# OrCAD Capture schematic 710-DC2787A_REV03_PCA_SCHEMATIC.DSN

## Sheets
1 PAGE5: size A
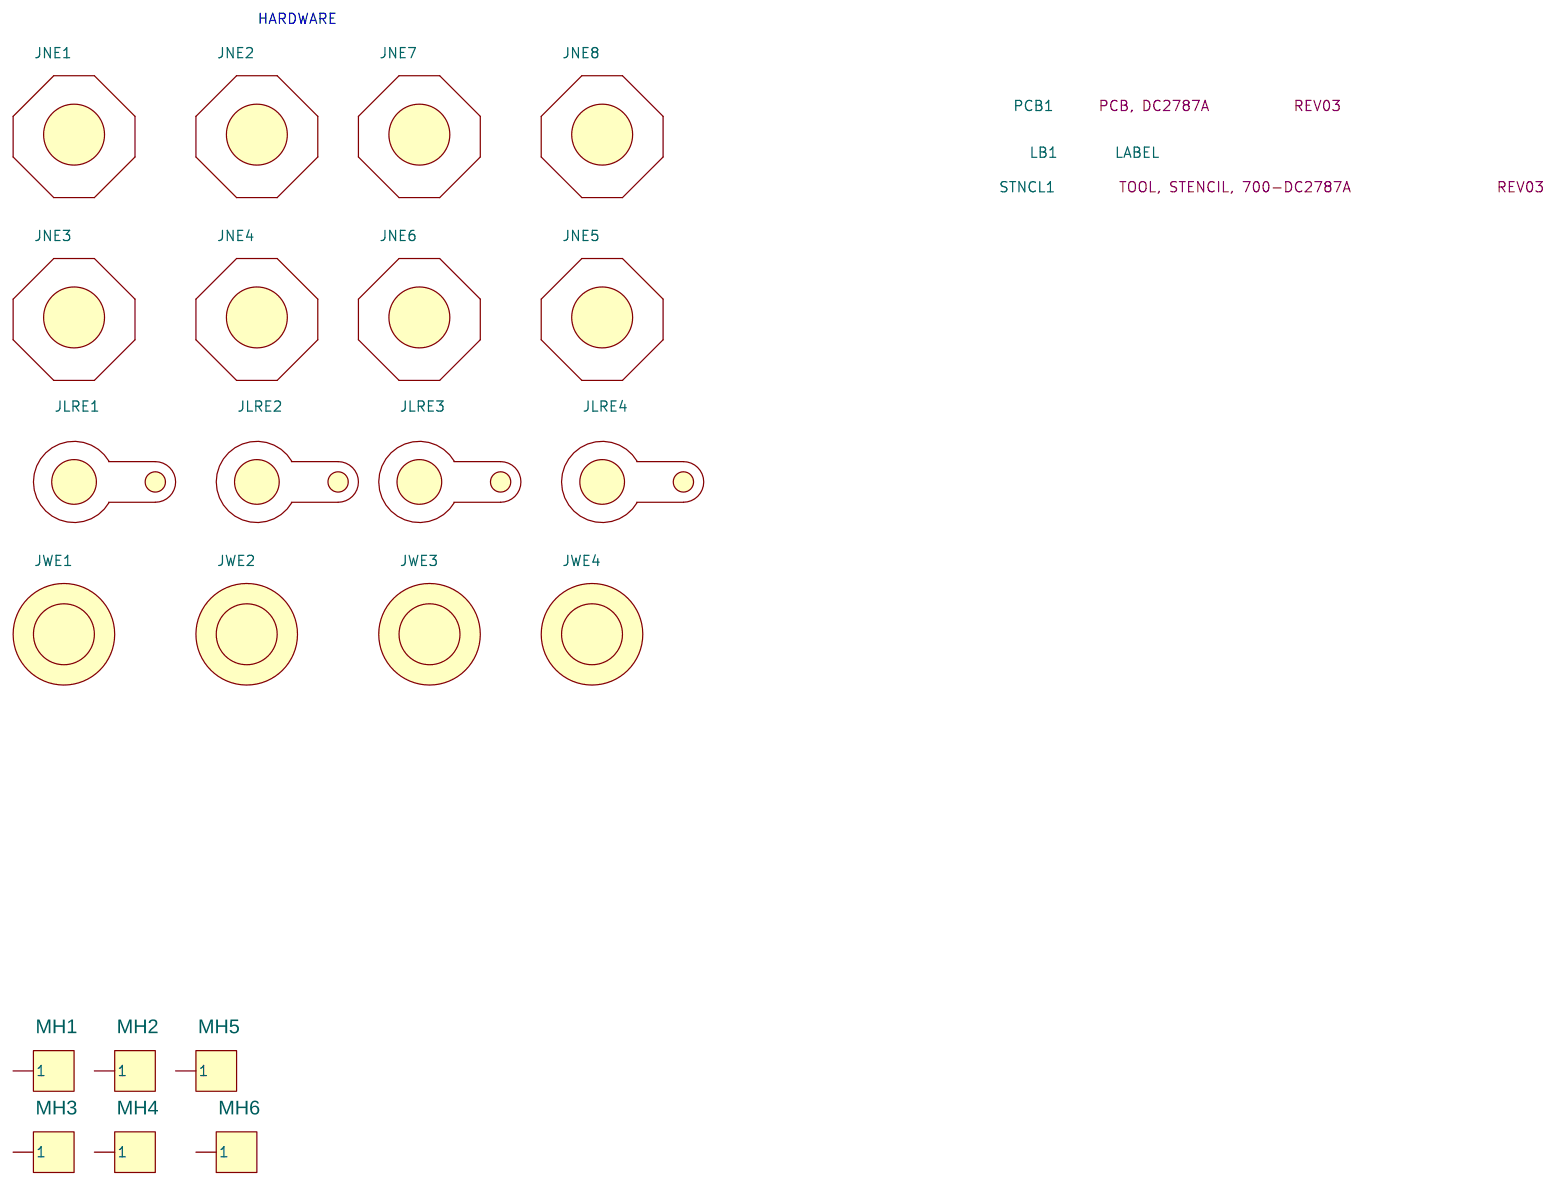
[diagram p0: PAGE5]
2 PAGE4: size Custom; note: HIGH EFFICIENCY, POLYPHASE HYBRID STEP-DOWN
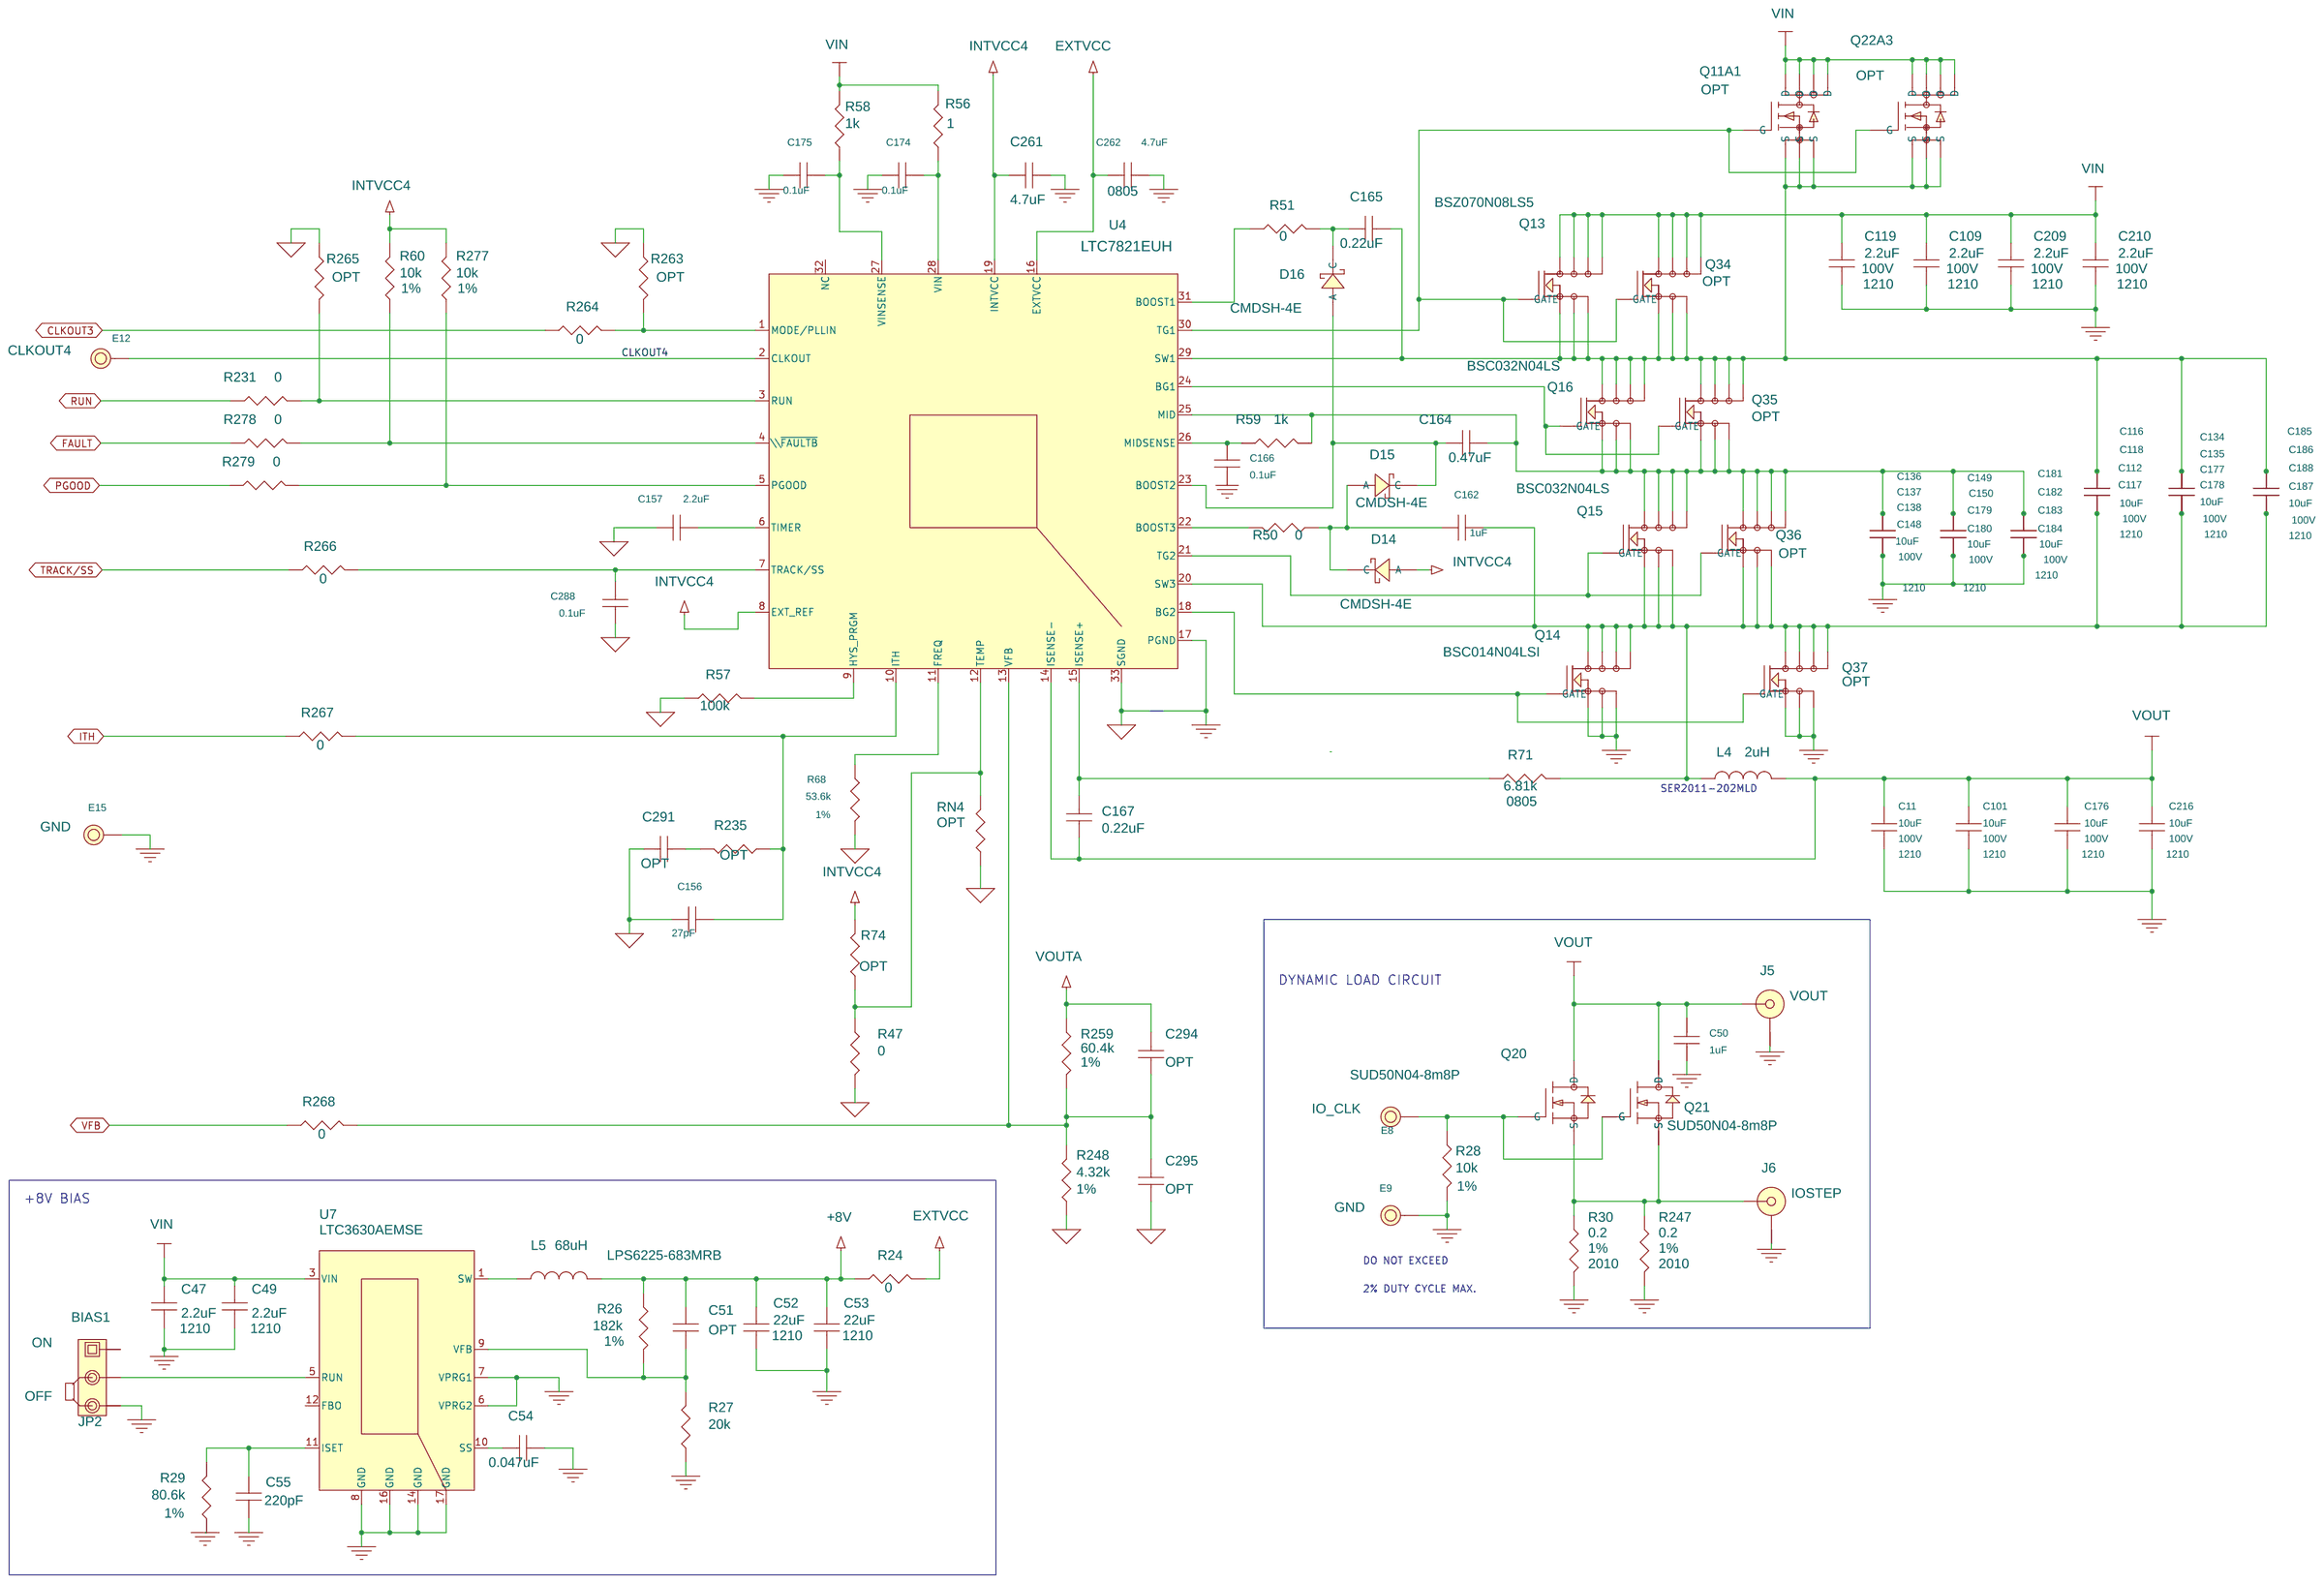
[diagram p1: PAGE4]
3 PAGE3: size Custom; title: HIGH EFFICIENCY, HIGH STEP-DOWN RATIO, SWITCHED CAPACITOR INVERTER; company: LINEAR TECHNOLOGY CORP.; note: DEMO BOARD BILL OF MATERIALS; note: HIGH EFFICIENCY, POLYPHASE HYBRID STEP-DOWN
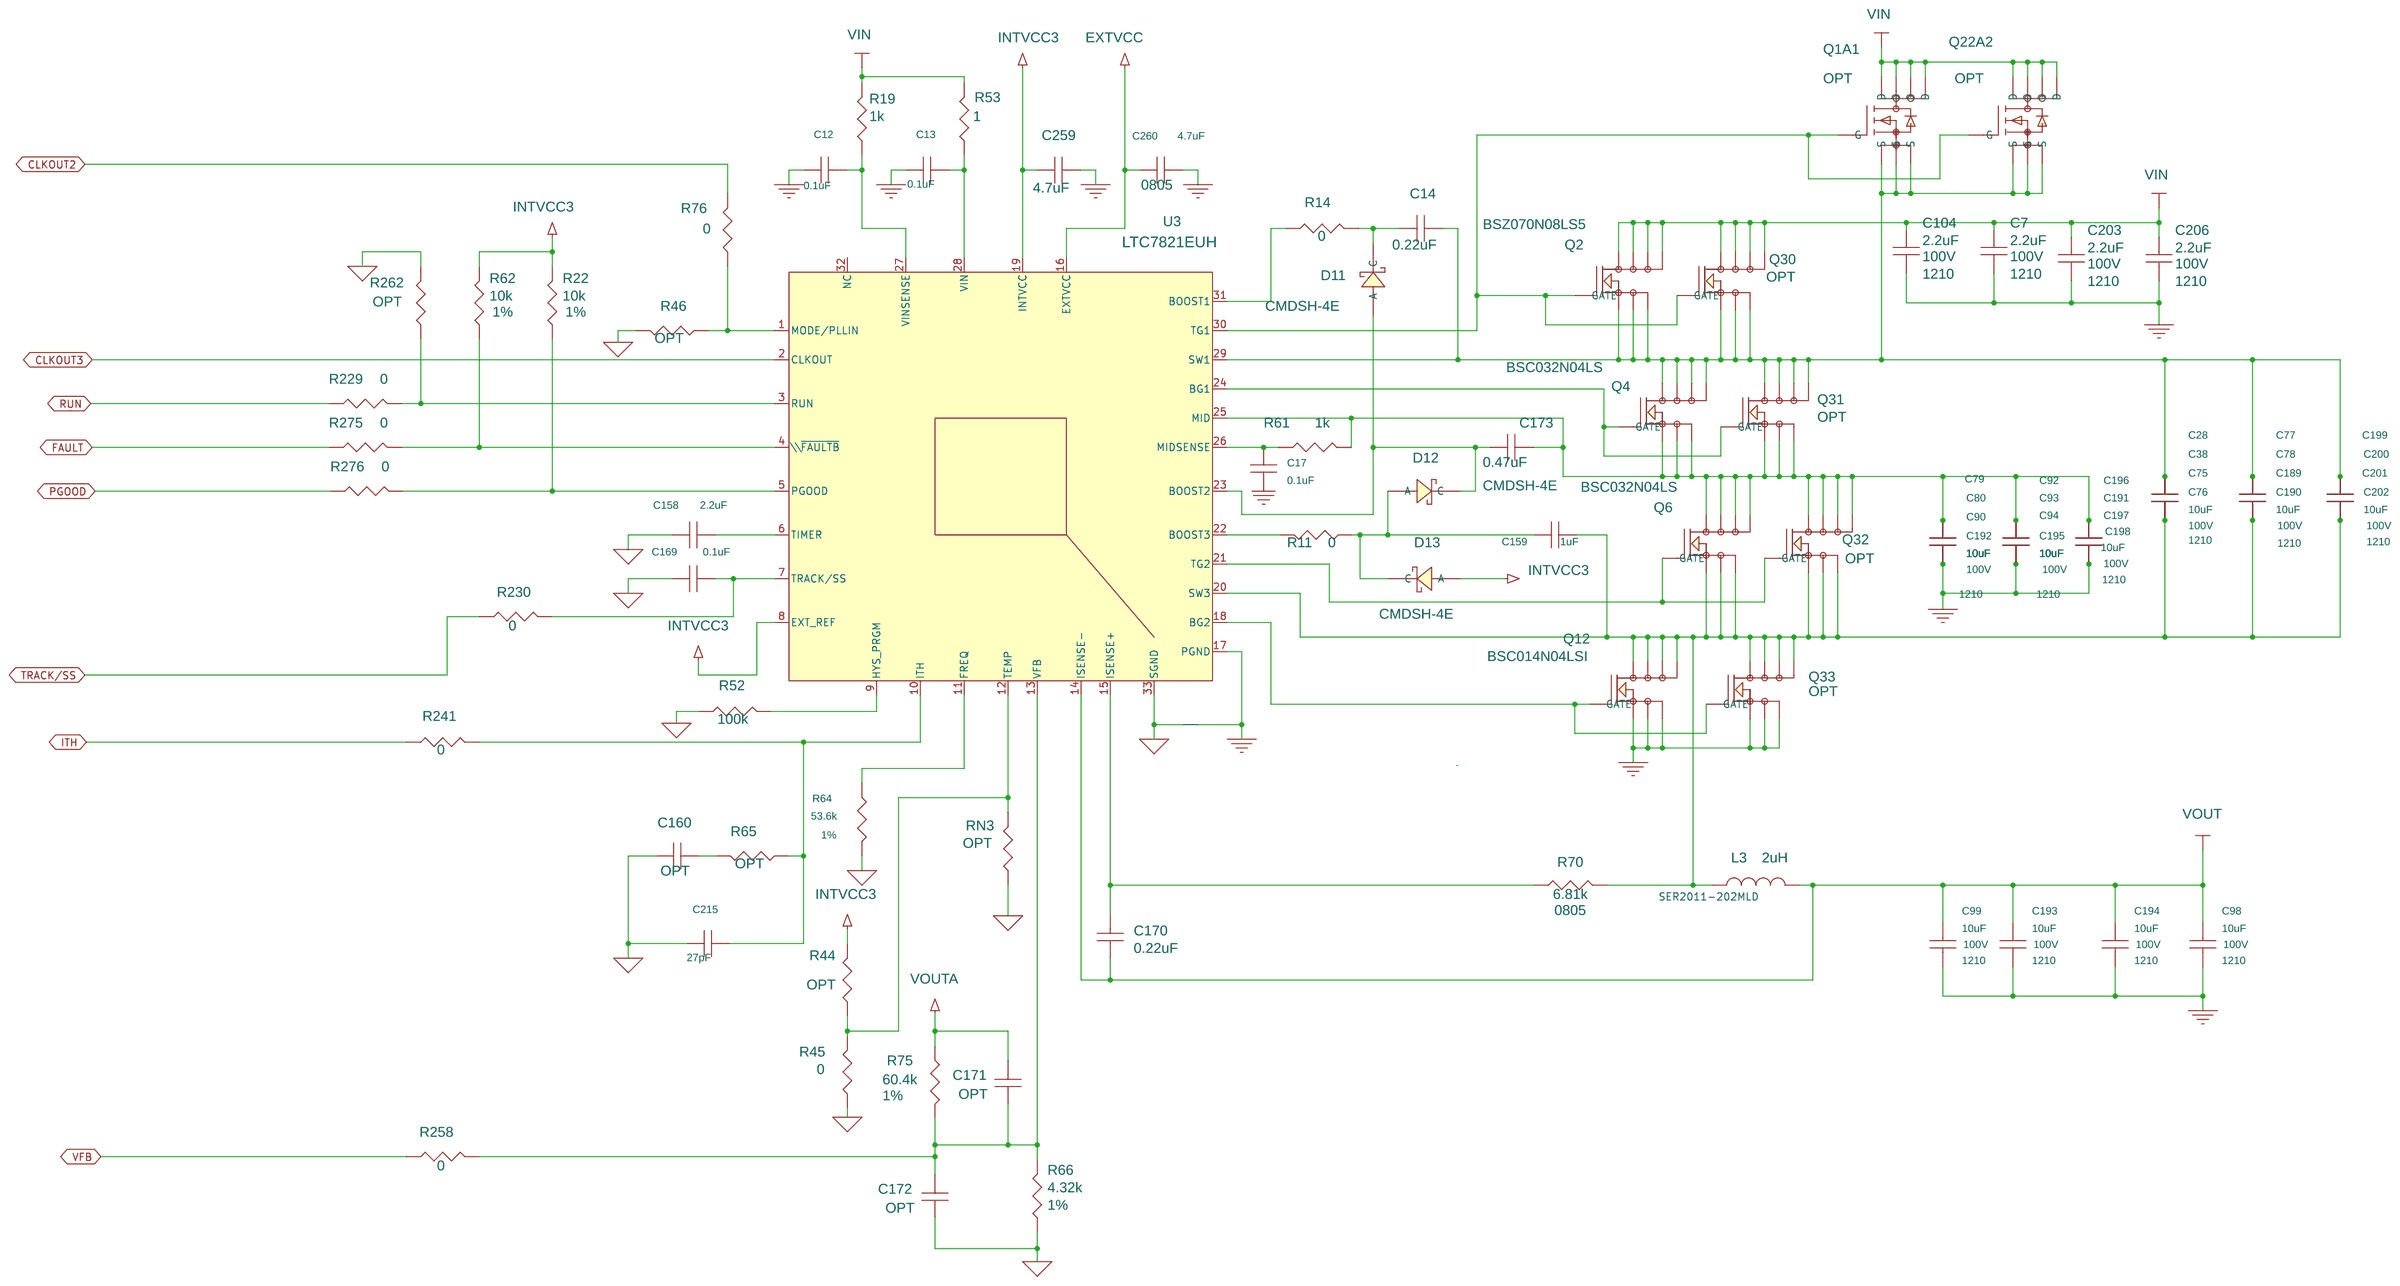
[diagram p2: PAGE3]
4 PAGE2: size Custom; note: HIGH EFFICIENCY, POLYPHASE HYBRID STEP-DOWN
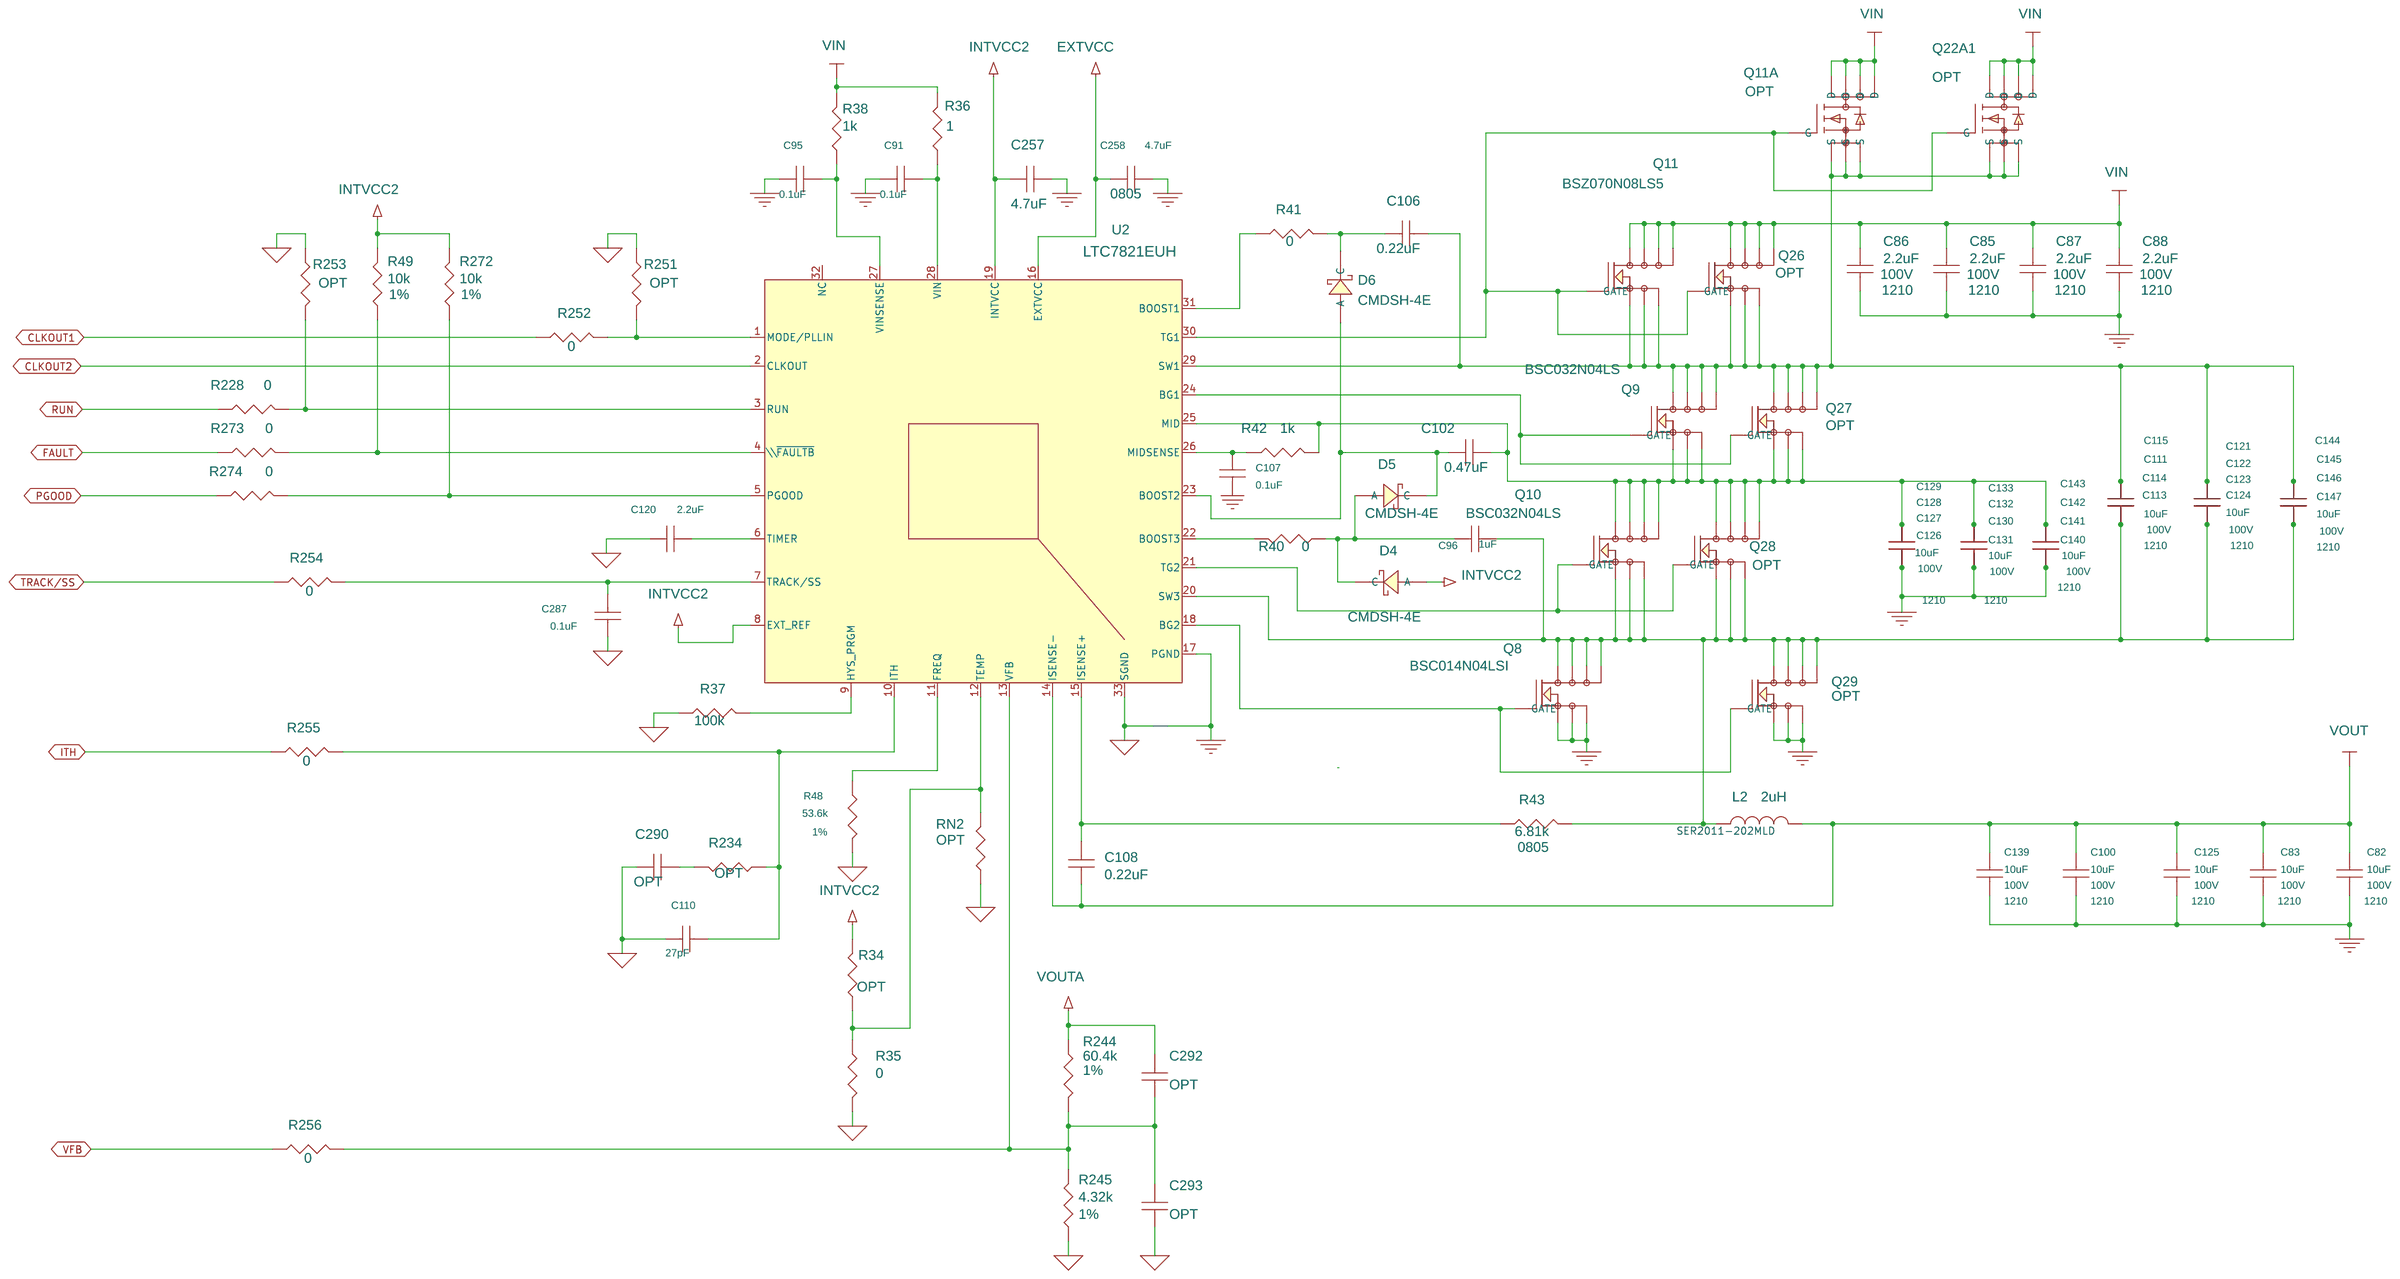
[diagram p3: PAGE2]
5 PAGE1: size Custom; title: HIGH EFFICIENCY, HIGH STEP-DOWN RATIO, SWITCHED CAPACITOR INVERTER; company: LINEAR TECHNOLOGY CORP.; note: DEMO BOARD BILL OF MATERIALS; note: HIGH EFFICIENCY, POLYPHASE HYBRID STEP-DOWN
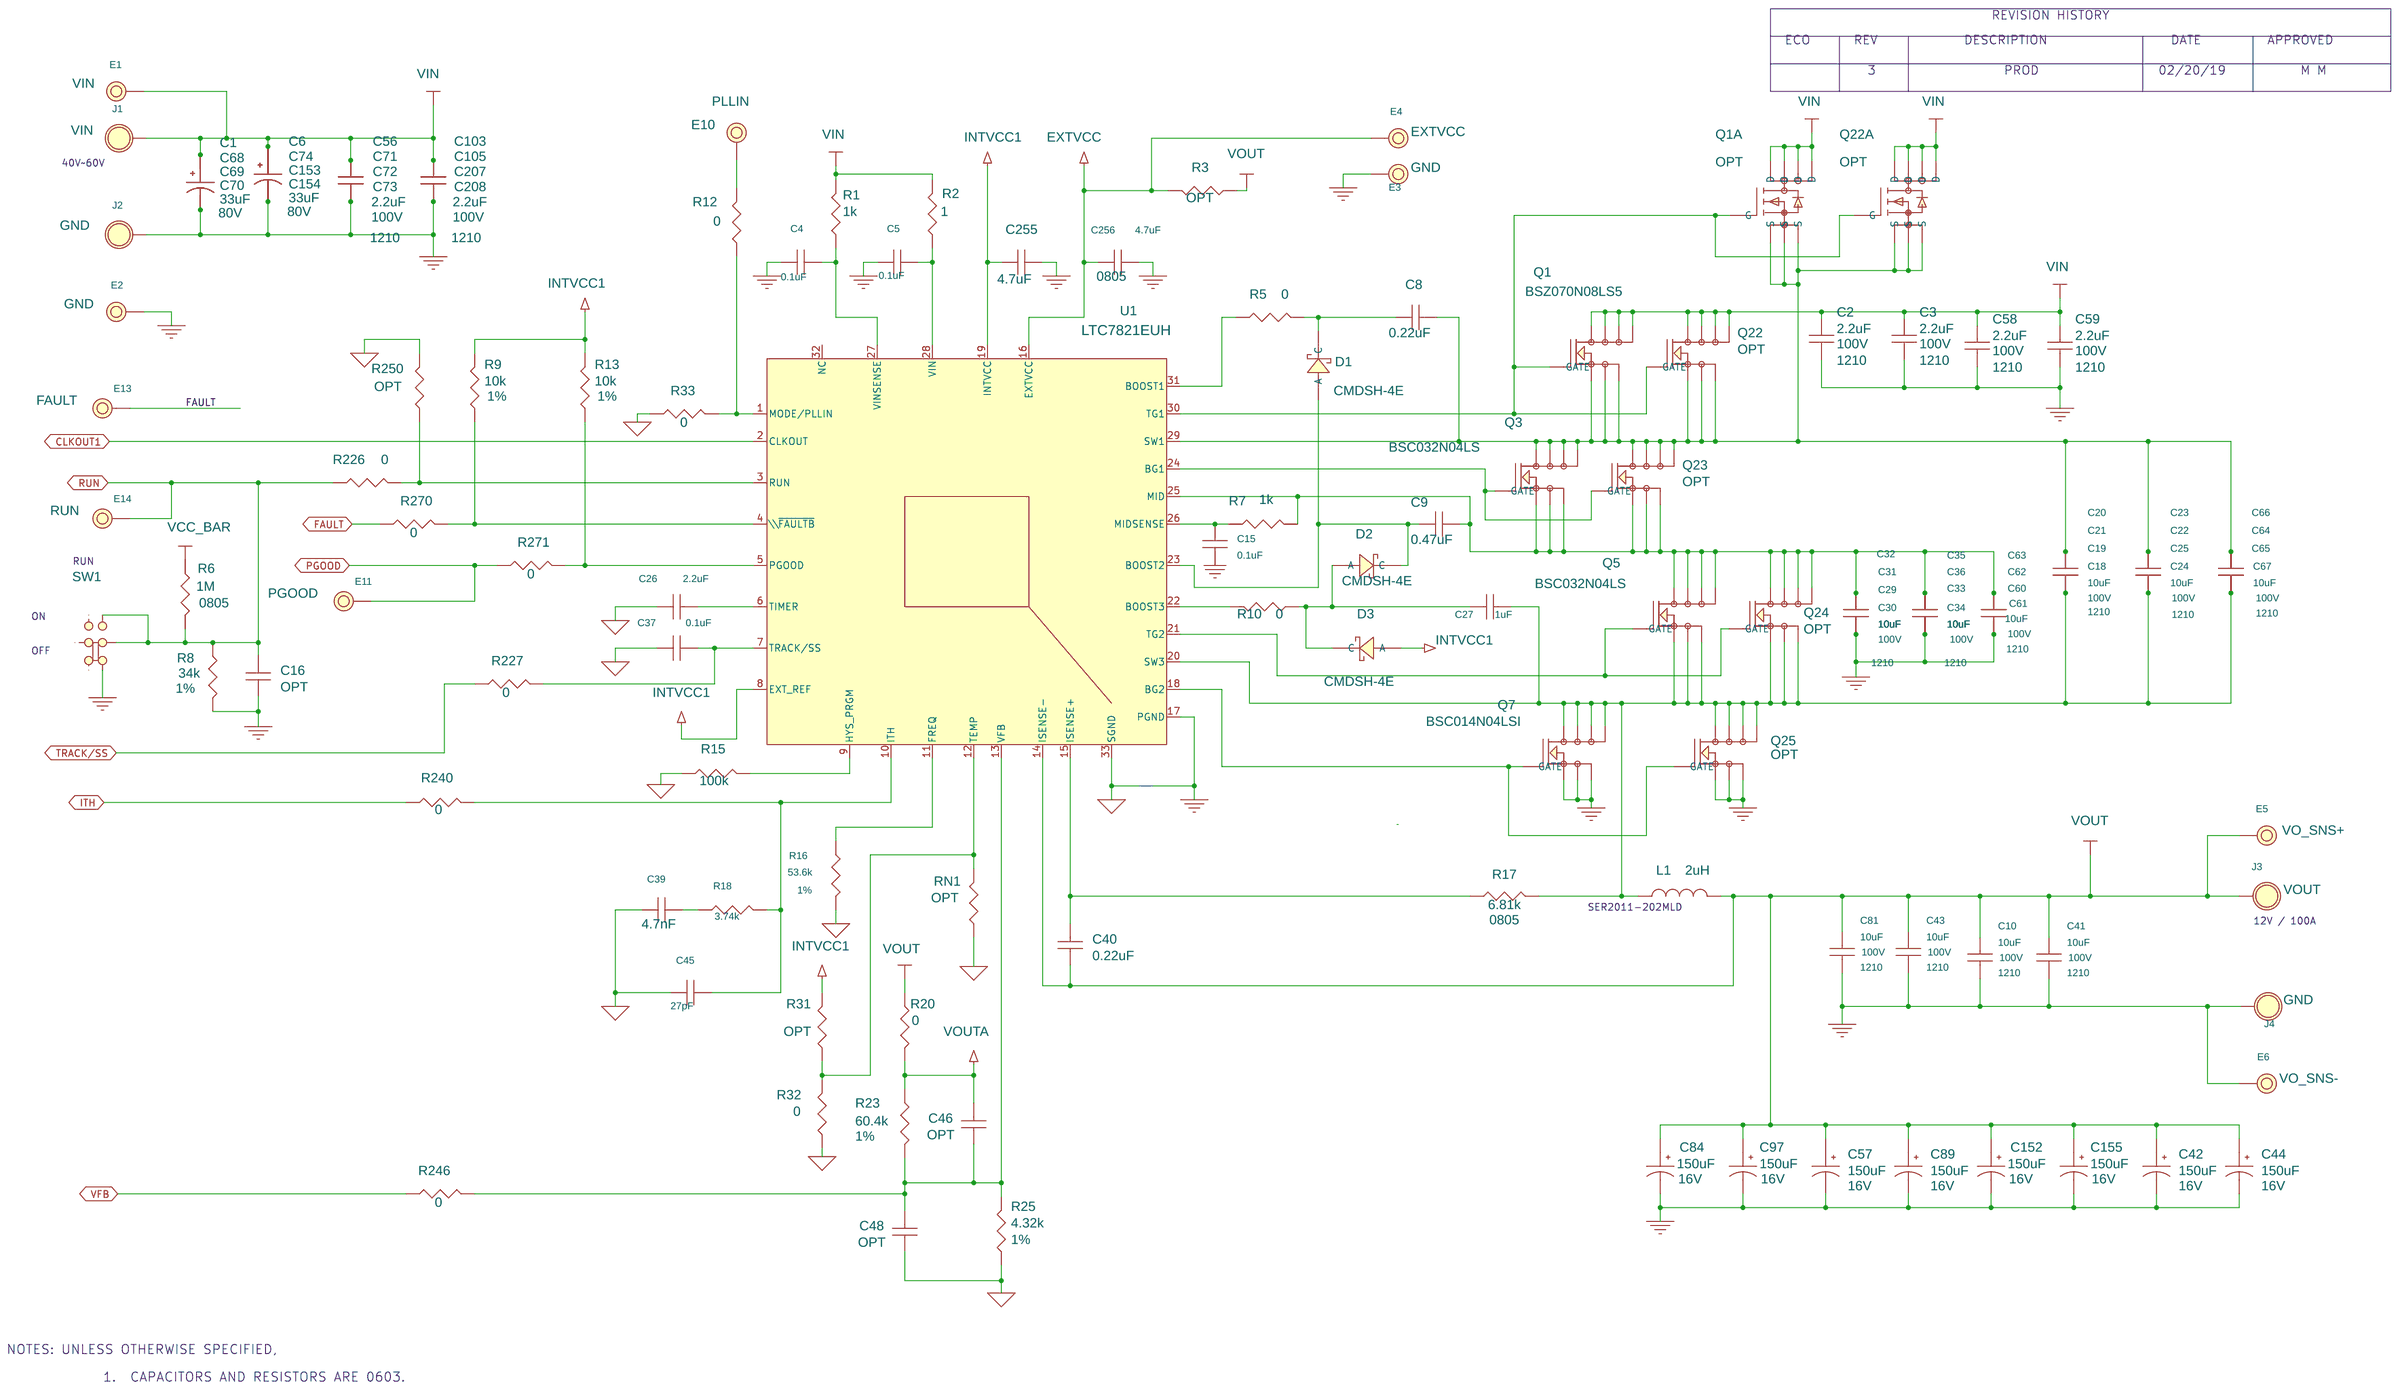
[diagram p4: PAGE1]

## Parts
sheet PAGE1
C1  33uF  [CAP\SANYO\10X10.2\CE]
C2  2.2uF  [CC1210N]
C3  2.2uF  [CC1210N]
C4  0.1uF  [CC0603N]
C5  0.1uF  [CC0603N]
C6  33uF  [CAP\SANYO\10X10.2\CE]
C8  0.22uF  [CC0603N]
C9  0.47uF  [CC0603N]
C10  10uF  [CC1210N]
C15  0.1uF  [CC0603N]
C16  OPT  [CC0603N]
C18  10uF  [CC1210N]
C19  10uF  [CC1210N]
C20  10uF  [CC1210N]
C21  10uF  [CC1210N]
C22  10uF  [CC1210N]
C23  10uF  [CC1210N]
C24  10uF  [CC1210N]
C25  10uF  [CC1210N]
C26  2.2uF  [CC0603N]
C27  1uF  [CC0603N]
C29  10uF  [CC1210N]
C30  10uF  [CC1210N]
C31  10uF  [CC1210N]
C32  10uF  [CC1210N]
C33  10uF  [CC1210N]
C34  10uF  [CC1210N]
C35  10uF  [CC1210N]
C36  10uF  [CC1210N]
C37  0.1uF  [CC0603N]
C39  4700pF  [CC0603N]
C40  0.22uF  [CC0603N]
C41  10uF  [CC1210N]
C42  150uF  [CAP\SANYO\SVPA_E7]
C43  10uF  [CC1210N]
C44  150uF  [CAP\SANYO\SVPA_E7]
C45  27pF  [CC0603N]
C46  OPT  [CC0603N]
C48  OPT  [CC0603N]
C56  2.2uF  [CC1210N]
C57  150uF  [CAP\SANYO\SVPA_E7]
C58  2.2uF  [CC1210N]
C59  2.2uF  [CC1210N]
C60  10uF  [CC1210N]
C61  10uF  [CC1210N]
C62  10uF  [CC1210N]
C63  10uF  [CC1210N]
C64  10uF  [CC1210N]
C65  10uF  [CC1210N]
C66  10uF  [CC1210N]
C67  10uF  [CC1210N]
C68  33uF  [CAP\SANYO\10X10.2\CE]
C69  33uF  [CAP\SANYO\10X10.2\CE]
C70  33uF  [CAP\SANYO\10X10.2\CE]
C71  2.2uF  [CC1210N]
C72  2.2uF  [CC1210N]
C73  2.2uF  [CC1210N]
C74  33uF  [CAP\SANYO\10X10.2\CE]
C81  10uF  [CC1210N]
C84  150uF  [CAP\SANYO\SVPA_E7]
C89  150uF  [CAP\SANYO\SVPA_E7]
C97  150uF  [CAP\SANYO\SVPA_E7]
C103  2.2uF  [CC1210N]
C105  2.2uF  [CC1210N]
C152  150uF  [CAP\SANYO\SVPA_E7]
C153  33uF  [CAP\SANYO\10X10.2\CE]
C154  33uF  [CAP\SANYO\10X10.2\CE]
C155  150uF  [CAP\SANYO\SVPA_E7]
C207  2.2uF  [CC1210N]
C208  2.2uF  [CC1210N]
C255  4.7uF  [CC0603N]
C256  4.7uF  [CC0805N]
D1  CMDSH-4E  [SOD-323N]
D2  CMDSH-4E  [SOD-323N]
D3  CMDSH-4E  [SOD-323N]
E1  TEST POINT  [MILLMAX2501]
E2  TEST POINT  [MILLMAX2501]
E3  TEST POINT  [MILLMAX2501]
E4  TEST POINT  [MILLMAX2501]
E5  TEST POINT  [MILLMAX2501]
E6  TEST POINT  [MILLMAX2501]
E10  TEST POINT  [MILLMAX2501]
E11  TEST POINT  [MILLMAX2501]
E13  TEST POINT  [MILLMAX2501]
E14  TEST POINT  [MILLMAX2501]
J1  STUD, FASTENER, #10-32  [PENN-KFH-032]
J2  STUD, FASTENER, #10-32  [PENN-KFH-032]
J3  STUD, FASTENER, #10-32  [PENN-KFH-032]
J4  STUD, FASTENER, #10-32  [PENN-KFH-032]
L1  2uH  [IND\CLCRFT\SER2010-102ML]
Q1  BSZ070N08LS5  [PWRPK_SO8]
Q1A  OPT  [XSTR\INFINEON\TSDSON-8]
Q3  BSC032N04LS  [INFINEON-PG-TDSON-8]
Q5  BSC032N04LS  [INFINEON-PG-TDSON-8]
Q7  BSC014N04LSI  [PWRPK_SO8]
Q22  OPT  [PWRPK_SO8]
Q22A  OPT  [XSTR\INFINEON\TSDSON-8]
Q23  OPT  [INFINEON-PG-TDSON-8]
Q24  OPT  [INFINEON-PG-TDSON-8]
Q25  OPT  [PWRPK_SO8]
R1  1k  [CR0603N]
R2  1  [CR0603N]
R3  OPT  [CR0603N]
R5  0  [CR0603N]
R6  1M  [CR0805N]
R7  1k  [CR0603N]
R8  34k  [CR0603N]
R9  10k  [CR0603N]
R10  0  [CR0603N]
R12  0  [CR0603N]
R13  10k  [CR0603N]
R15  100k  [CR0603N]
R16  53.6k  [CR0603N]
R17  6.81k  [CR0805N]
R18  3.74k  [CR0603N]
R20  0  [CR0603N]
R23  60.4k  [CR0603N]
R25  4.32k  [CR0603N]
R31  OPT  [CR0603N]
R32  0  [CR0603N]
R33  0  [CR0603N]
R226  0  [CR0603N]
R227  0  [CR0603N]
R240  0  [CR0603N]
R246  0  [CR0603N]
R250  OPT  [CR0603N]
R270  0  [CR0603N]
R271  0  [CR0603N]
RN1  OPT  [CR0603N]
SW1  DPDT  [C&K-JS202011CQN]
U1  LTC7821EUH  [LTC-UH-32-1693]
sheet PAGE2
C82  10uF  [CC1210N]
C83  10uF  [CC1210N]
C85  2.2uF  [CC1210N]
C86  2.2uF  [CC1210N]
C87  2.2uF  [CC1210N]
C88  2.2uF  [CC1210N]
C91  0.1uF  [CC0603N]
C95  0.1uF  [CC0603N]
C96  1uF  [CC0603N]
C100  10uF  [CC1210N]
C102  0.47uF  [CC0603N]
C106  0.22uF  [CC0603N]
C107  0.1uF  [CC0603N]
C108  0.22uF  [CC0603N]
C110  27pF  [CC0603N]
C111  10uF  [CC1210N]
C113  10uF  [CC1210N]
C114  10uF  [CC1210N]
C115  10uF  [CC1210N]
C120  2.2uF  [CC0603N]
C121  10uF  [CC1210N]
C122  10uF  [CC1210N]
C123  10uF  [CC1210N]
C124  10uF  [CC1210N]
C125  10uF  [CC1210N]
C126  10uF  [CC1210N]
C127  10uF  [CC1210N]
C128  10uF  [CC1210N]
C129  10uF  [CC1210N]
C130  10uF  [CC1210N]
C131  10uF  [CC1210N]
C132  10uF  [CC1210N]
C133  10uF  [CC1210N]
C139  10uF  [CC1210N]
C140  10uF  [CC1210N]
C141  10uF  [CC1210N]
C142  10uF  [CC1210N]
C143  10uF  [CC1210N]
C144  10uF  [CC1210N]
C145  10uF  [CC1210N]
C146  10uF  [CC1210N]
C147  10uF  [CC1210N]
C257  4.7uF  [CC0603N]
C258  4.7uF  [CC0805N]
C287  0.1uF  [CC0603N]
C290  OPT  [CC0603N]
C292  OPT  [CC0603N]
C293  OPT  [CC0603N]
D4  CMDSH-4E  [SOD-323N]
D5  CMDSH-4E  [SOD-323N]
D6  CMDSH-4E  [SOD-323N]
L2  2uH  [IND\CLCRFT\SER2010-102ML]
Q8  BSC014N04LSI  [PWRPK_SO8]
Q9  BSC032N04LS  [INFINEON-PG-TDSON-8]
Q10  BSC032N04LS  [INFINEON-PG-TDSON-8]
Q11  BSZ070N08LS5  [PWRPK_SO8]
Q11A  OPT  [XSTR\INFINEON\TSDSON-8]
Q22A1  OPT  [XSTR\INFINEON\TSDSON-8]
Q26  OPT  [PWRPK_SO8]
Q27  OPT  [INFINEON-PG-TDSON-8]
Q28  OPT  [INFINEON-PG-TDSON-8]
Q29  OPT  [PWRPK_SO8]
R34  OPT  [CR0603N]
R35  0  [CR0603N]
R36  1  [CR0603N]
R37  100k  [CR0603N]
R38  1k  [CR0603N]
R40  0  [CR0603N]
R41  0  [CR0603N]
R42  1k  [CR0603N]
R43  6.81k  [CR0805N]
R48  53.6k  [CR0603N]
R49  10k  [CR0603N]
R228  0  [CR0603N]
R234  OPT  [CR0603N]
R244  60.4k  [CR0603N]
R245  4.32k  [CR0603N]
R251  OPT  [CR0603N]
R252  0  [CR0603N]
R253  OPT  [CR0603N]
R254  0  [CR0603N]
R255  0  [CR0603N]
R256  0  [CR0603N]
R272  10k  [CR0603N]
R273  0  [CR0603N]
R274  0  [CR0603N]
RN2  OPT  [CR0603N]
U2  LTC7821EUH  [LTC-UH-32-1693]
sheet PAGE3
C7  2.2uF  [CC1210N]
C12  0.1uF  [CC0603N]
C13  0.1uF  [CC0603N]
C14  0.22uF  [CC0603N]
C17  0.1uF  [CC0603N]
C28  10uF  [CC1210N]
C38  10uF  [CC1210N]
C75  10uF  [CC1210N]
C76  10uF  [CC1210N]
C77  10uF  [CC1210N]
C78  10uF  [CC1210N]
C79  10uF  [CC1210N]
C80  10uF  [CC1210N]
C90  10uF  [CC1210N]
C92  10uF  [CC1210N]
C93  10uF  [CC1210N]
C94  10uF  [CC1210N]
C98  10uF  [CC1210N]
C99  10uF  [CC1210N]
C104  2.2uF  [CC1210N]
C158  2.2uF  [CC0603N]
C159  1uF  [CC0603N]
C160  OPT  [CC0603N]
C169  0.1uF  [CC0603N]
C170  0.22uF  [CC0603N]
C171  OPT  [CC0603N]
C172  OPT  [CC0603N]
C173  0.47uF  [CC0603N]
C189  10uF  [CC1210N]
C190  10uF  [CC1210N]
C191  10uF  [CC1210N]
C192  10uF  [CC1210N]
C193  10uF  [CC1210N]
C194  10uF  [CC1210N]
C195  10uF  [CC1210N]
C196  10uF  [CC1210N]
C197  10uF  [CC1210N]
C198  10uF  [CC1210N]
C199  10uF  [CC1210N]
C200  10uF  [CC1210N]
C201  10uF  [CC1210N]
C202  10uF  [CC1210N]
C203  2.2uF  [CC1210N]
C206  2.2uF  [CC1210N]
C215  27pF  [CC0603N]
C259  4.7uF  [CC0603N]
C260  4.7uF  [CC0805N]
D11  CMDSH-4E  [SOD-323N]
D12  CMDSH-4E  [SOD-323N]
D13  CMDSH-4E  [SOD-323N]
L3  2uH  [IND\CLCRFT\SER2010-102ML]
Q1A1  OPT  [XSTR\INFINEON\TSDSON-8]
Q2  BSZ070N08LS5  [PWRPK_SO8]
Q4  BSC032N04LS  [INFINEON-PG-TDSON-8]
Q6  BSC032N04LS  [INFINEON-PG-TDSON-8]
Q12  BSC014N04LSI  [PWRPK_SO8]
Q22A2  OPT  [XSTR\INFINEON\TSDSON-8]
Q30  OPT  [PWRPK_SO8]
Q31  OPT  [INFINEON-PG-TDSON-8]
Q32  OPT  [INFINEON-PG-TDSON-8]
Q33  OPT  [PWRPK_SO8]
R11  0  [CR0603N]
R14  0  [CR0603N]
R19  1k  [CR0603N]
R22  10k  [CR0603N]
R44  OPT  [CR0603N]
R45  0  [CR0603N]
R46  OPT  [CR0603N]
R52  100k  [CR0603N]
R53  1  [CR0603N]
R61  1k  [CR0603N]
R62  10k  [CR0603N]
R64  53.6k  [CR0603N]
R65  OPT  [CR0603N]
R66  4.32k  [CR0603N]
R70  6.81k  [CR0805N]
R75  60.4k  [CR0603N]
R76  0  [CR0603N]
R229  0  [CR0603N]
R230  0  [CR0603N]
R241  0  [CR0603N]
R258  0  [CR0603N]
R262  OPT  [CR0603N]
R275  0  [CR0603N]
R276  0  [CR0603N]
RN3  OPT  [CR0603N]
U3  LTC7821EUH  [LTC-UH-32-1693]
sheet PAGE4
C11  10uF  [CC1210N]
C47  2.2uF  [CC1210N]
C49  2.2uF  [CC1210N]
C50  1uF  [CC0603N]
C51  OPT  [CC0603N]
C52  22uF  [CC1210N]
C53  22uF  [CC1210N]
C54  0.047uF  [CC0603N]
C55  220pF  [CC0603N]
C101  10uF  [CC1210N]
C109  2.2uF  [CC1210N]
C112  10uF  [CC1210N]
C116  10uF  [CC1210N]
C117  10uF  [CC1210N]
C118  10uF  [CC1210N]
C119  2.2uF  [CC1210N]
C134  10uF  [CC1210N]
C135  10uF  [CC1210N]
C136  10uF  [CC1210N]
C137  10uF  [CC1210N]
C138  10uF  [CC1210N]
C148  10uF  [CC1210N]
C149  10uF  [CC1210N]
C150  10uF  [CC1210N]
C156  27pF  [CC0603N]
C157  2.2uF  [CC0603N]
C162  1uF  [CC0603N]
C164  0.47uF  [CC0603N]
C165  0.22uF  [CC0603N]
C166  0.1uF  [CC0603N]
C167  0.22uF  [CC0603N]
C174  0.1uF  [CC0603N]
C175  0.1uF  [CC0603N]
C176  10uF  [CC1210N]
C177  10uF  [CC1210N]
C178  10uF  [CC1210N]
C179  10uF  [CC1210N]
C180  10uF  [CC1210N]
C181  10uF  [CC1210N]
C182  10uF  [CC1210N]
C183  10uF  [CC1210N]
C184  10uF  [CC1210N]
C185  10uF  [CC1210N]
C186  10uF  [CC1210N]
C187  10uF  [CC1210N]
C188  10uF  [CC1210N]
C209  2.2uF  [CC1210N]
C210  2.2uF  [CC1210N]
C216  10uF  [CC1210N]
C261  4.7uF  [CC0603N]
C262  4.7uF  [CC0805N]
C288  0.1uF  [CC0603N]
C291  OPT  [CC0603N]
C294  OPT  [CC0603N]
C295  OPT  [CC0603N]
D14  CMDSH-4E  [SOD-323N]
D15  CMDSH-4E  [SOD-323N]
D16  CMDSH-4E  [SOD-323N]
E8  TEST POINT  [MILLMAX2501]
E9  TEST POINT  [MILLMAX2501]
E12  TEST POINT  [MILLMAX2501]
E15  TEST POINT  [MILLMAX2501]
J5  RF, BNC  [CONNEX-112404]
J6  RF, BNC  [CONNEX-112404]
JP2  HDR  [HD1X3-079]
L4  2uH  [IND\CLCRFT\SER2010-102ML]
L5  68uH  [COILCRAFT-LPS6225]
Q11A1  OPT  [XSTR\INFINEON\TSDSON-8]
Q13  BSZ070N08LS5  [PWRPK_SO8]
Q14  BSC014N04LSI  [PWRPK_SO8]
Q15  BSC032N04LS  [INFINEON-PG-TDSON-8]
Q16  BSC032N04LS  [INFINEON-PG-TDSON-8]
Q20  SUD50N04-8m8P  [TO-252-3N]
Q21  SUD50N04-8m8P  [TO-252-3N]
Q22A3  OPT  [XSTR\INFINEON\TSDSON-8]
Q34  OPT  [PWRPK_SO8]
Q35  OPT  [INFINEON-PG-TDSON-8]
Q36  OPT  [INFINEON-PG-TDSON-8]
Q37  OPT  [PWRPK_SO8]
R24  0  [CR0603N]
R26  182k  [CR0603N]
R27  20k  [CR0603N]
R28  10k  [CR0603N]
R29  80.6k  [CR0603N]
R30  0.2  [CR2010N]
R47  0  [CR0603N]
R50  0  [CR0603N]
R51  0  [CR0603N]
R56  1  [CR0603N]
R57  100k  [CR0603N]
R58  1k  [CR0603N]
R59  1k  [CR0603N]
R60  10k  [CR0603N]
R68  53.6k  [CR0603N]
R71  6.81k  [CR0805N]
R74  OPT  [CR0603N]
R231  0  [CR0603N]
R235  OPT  [CR0603N]
R247  0.2  [CR2010N]
R248  4.32k  [CR0603N]
R259  60.4k  [CR0603N]
R263  OPT  [CR0603N]
R264  0  [CR0603N]
R265  OPT  [CR0603N]
R266  0  [CR0603N]
R267  0  [CR0603N]
R268  0  [CR0603N]
R277  10k  [CR0603N]
R278  0  [CR0603N]
R279  0  [CR0603N]
RN4  OPT  [CR0603N]
U4  LTC7821EUH  [LTC-UH-32-1693]
U7  LTC3630AEMSE  [LTC-MSE-16-1871]
XJP2  SHUNT
sheet PAGE5
JLRE1  RING, LUG, CRIMP
JLRE2  RING, LUG, CRIMP
JLRE3  RING, LUG, CRIMP
JLRE4  RING, LUG, CRIMP
JNE1  NUT,HEX
JNE2  NUT,HEX
JNE3  NUT,HEX
JNE4  NUT,HEX
JNE5  NUT,HEX
JNE6  NUT,HEX
JNE7  NUT,HEX
JNE8  NUT,HEX
JWE1  WASHER
JWE2  WASHER
JWE3  WASHER
JWE4  WASHER
LB1  LABEL  [895-0154_REV01]
MH1  STANDOFF  [KEYSTONE_8829-8834]
MH2  STANDOFF  [KEYSTONE_8829-8834]
MH3  STANDOFF  [KEYSTONE_8829-8834]
MH4  STANDOFF  [KEYSTONE_8829-8834]
MH5  STANDOFF  [KEYSTONE_8829-8834]
MH6  STANDOFF  [KEYSTONE_8829-8834]
PCB1  PCB, DC2787A
STNCL1  TOOL, STENCIL, 700-DC2787A

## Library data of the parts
C1 C6 C68-C70 C74 C153 C154 = CAP_P: CAP.,33uF,ALUM. ELECT.,80V,20%,10x10.2mm SMD, RADIAL,AEC-Q200; CLASS: DISCRETE; Dielectric Type: ALUM. ELECT.; Manufacturer: PANASONIC; Manufacturer PN: EEHZA1K330P; PART_NUMBER: 150-2503; Package Size: 10x10.2mm SMD, RADIAL; Part Number: PANASONIC EEHZA1K330P; Rated Voltage: 80V; Tolerance: 20%
C2 C3 C7 C47 C49 C56 C58 C59 C71-C73 C85-C88 C104 C105 C119 C203 C206 C207 C209 C210 = CAP: CAP.,2.2uF,X7R,100V,10%,1210; CLASS: DISCRETE; Dielectric Type: X7R; FPLIST: CC1210N,CC1210L,CC1210M; Manufacturer: MURATA; Manufacturer PN: GRM32DR72A225KA12K; PART_NUMBER: 150-2506; Package Size: 1210; Part Number: MURATA GRM32DR72A225KA12K; Rated Voltage: 100V; Tolerance: 10%
C4 C5 C12 C13 C15 C17 C37 C91 C95 C107 C166 C169 C174 C175 = CAP: CAP.,0.1uF,X7S,100V,10%,0603; CLASS: DISCRETE; Dielectric Type: X7S; FPLIST: CC0603N,CC0603L,CC0603M; Manufacturer: TDK; Manufacturer PN: C1608X7S2A104K080AB; PART_NUMBER: 150-0493; Package Size: 0603; Part Number: MURATA GRM188R72A104KA35D; Rated Voltage: 100V; Tolerance: 10%
C8 C14 C40 C106 C108 C165 C167 C170 = CAP: CAP.,0.22uF,X7R,25V,10%,0603; CLASS: DISCRETE; Dielectric Type: X7R; FPLIST: CC0603N,CC0603L,CC0603M; Manufacturer: MURATA; Manufacturer PN: GRM188R71E224KA88D; PART_NUMBER: 150-0320; Package Size: 0603; Part Number: MURATA GRM188R71E224KA88D; Rated Voltage: 25V; Tolerance: 10%
C9 C102 C164 C173 = CAP: CAP.,0.47uF,X7R,25V,10%,0603; CLASS: DISCRETE; Dielectric Type: X7R; FPLIST: CC0603N,CC0603L,CC0603M; Manufacturer: AVX; Manufacturer PN: 06033C474KAT2A; PART_NUMBER: 150-2369; Package Size: 0603; Part Number: MURATA GRM188R71E474KA12D; Rated Voltage: 25V; Tolerance: 10%
C10 C11 C18-C25 C28-C36 C38 C41 C43 C60-C67 C75-C83 C90 C92-C94 C98-C101 C111-C118 C121-C150 C176-C202 C216 = CAP: CAP.,10uF,X7S,100V,10%,1210; CLASS: DISCRETE; Dielectric Type: X7S; FPLIST: CC1210N,CC1210L,CC1210M; Inventory Qty: 1000; Manufacturer: MURATA; Manufacturer PN: GRM32EC72A106KE05L; PART_NUMBER: 150-2537; Package Size: 1210; Package Type: Surface Mount, MLCC; Part Number: MURATA GRM32ER71H106KA12L; Rated Voltage: 100V; Temperature Coefficient: X7S; Tolerance: 10%; UserField01: NO SUBS. ALLOWED
C16 C46 C48 C51 C160 C171 C172 C290-C295 = CAP: CAP., OPTION, 0603; CLASS: DISCRETE; FPLIST: CC0603N,CC0603L,CC0603M; PART_NUMBER: 150-3038; Package Size: 0603; Package Type: SMD; Part Number: OPTION; UserField01: OPTION
C26 C120 C157 C158 = CAP: CAP.,2.2uF,X5R,25V,10%,0603; CLASS: DISCRETE; Dielectric Type: X5R; FPLIST: CC0603N,CC0603L,CC0603M; Manufacturer: MURATA; Manufacturer PN: GRM188R61E225KA12D; PART_NUMBER: 150-3289; Package Size: 0603; Part Number: MURATA GRM188R61E105KA12D; Rated Voltage: 25V; Tolerance: 10%
C27 C50 C96 C159 C162 = CAP: CAP.,1uF,X7R,25V,10%,0603,AEC-Q200; CLASS: DISCRETE; Dielectric Type: X7R; FPLIST: CC0603N,CC0603L,CC0603M; Manufacturer: TDK; Manufacturer PN: CGA3E1X7R1E105K080AC; PART_NUMBER: 150-0291; Package Size: 0603; Part Number: MURATA GRM188R61E105KA12D; Rated Voltage: 25V; Tolerance: 10%
C39 = CAP: CAP.,4700pF,X7R,25V,10%,0603; BOM Notes: 4.7nF; CLASS: DISCRETE; Dielectric Type: X7R; FPLIST: CC0603N,CC0603L,CC0603M; Inventory Qty: 800; Manufacturer: AVX; Manufacturer PN: 06033C472KAT2A; PART_NUMBER: 150-3386; Package Size: 0603; Part Number: MURATA GRM188R71H682KA01D; Rated Voltage: 25V; Tolerance: 10%
C42 C44 C57 C84 C89 C97 C152 C155 = CAP_P: CAP.,150uF,ALUM./OS-CON,16V,20%,8x6.9mm SMD, RADIAL; CLASS: DISCRETE; Dielectric Type: ALUM./OS-CON; Manufacturer: PANASONIC; Manufacturer PN: 16SVPC150M; PART_NUMBER: 150-2273; Package Size: 8x6.9mm SMD, RADIAL; Part Number: PANASONIC 16SVPC150M; Rated Voltage: 16V; Tolerance: 20%
C45 C110 C156 C215 = CAP: CAP.,27pF,C0G,250V,5%,0603; CLASS: DISCRETE; Dielectric Type: C0G; FPLIST: CC0603N,CC0603L,CC0603M; Manufacturer: MURATA; Manufacturer PN: GQM1875C2E270JB12D; PART_NUMBER: 150-3313; Package Size: 0603; Part Number: MURATA GRM1885C2A101JA01D; Rated Voltage: 250V; Tolerance: 5%
C103 C109 C208 = CAP: CAP.,2.2uF,X7R,100V,10%,1210; CLASS: DISCRETE; Dielectric Type: X7R; FPLIST: CC1210N,CC1210L,CC1210M; Manufacturer: AVX; Manufacturer PN: 12101C225KAT2A; PART_NUMBER: 150-2506; Package Size: 1210; Part Number: MURATA GRM32DR72A225KA12K; Rated Voltage: 100V; Tolerance: 10%
C255 C257 C259 C261 = CAP: CAP.,4.7uF,X5R,16V,10%,0603; CLASS: DISCRETE; Dielectric Type: X5R; FPLIST: CC0603N,CC0603L,CC0603M; Manufacturer: MURATA; Manufacturer PN: GRM188R61C475KE11D; PART_NUMBER: 150-3182; Package Size: 0603; Part Number: MURATA GRM188R61C475KE11D; Rated Voltage: 16V; Tolerance: 10%
C256 C258 C260 C262 = CAP: CAP.,4.7uF,X5R,50V,10%,0805; CLASS: DISCRETE; Dielectric Type: X5R; FPLIST: CC0805N,CC0805L,CC0805M; Inventory Qty: 1200; Manufacturer: MURATA; Manufacturer PN: GRM21BR61H475KE51L; PART_NUMBER: 150-0172; Package Size: 0805; Part Number: MURATA GRM188R61C475KE11D; Rated Voltage: 50V; Tolerance: 10%
D1-D6 D11-D15 = DIODE_SCHOTTKY_A: DIODE,SCHOTTKY,40V,250mW,SOD-323; CLASS: DISCRETE; FPLIST: SOD323,SOD-323N,SOD-323M; Manufacturer: CENTRAL SEMI.; Manufacturer PN: CMDSH-4E TR Lead Free; PART_NUMBER: 210-0247; Package Type: SOD-323; Part Number: CENTRAL SEMI. CMDSH-4E TR; Rated Voltage: 40V; Rated Voltage or Zener Voltage: 40V
E1 = TESTPOINT_.219_MILL-MAX_2501: TEST POINT,TURRET,0.094",MTG. HOLE; 1st Part Field: VIN; CLASS: IO; FPLIST: MILLMAX2501,MILLMAX2501_ALT1; Manufacturer: MILL-MAX; Manufacturer PN: 2501-2-00-80-00-00-07-0; PART_NUMBER: 260-0003; Part Number: MILL-MAX 2501-2-00-80-00-00-07-0
E2 E3 E9 E15 = TESTPOINT_.219_MILL-MAX_2501: TEST POINT,TURRET,0.094",MTG. HOLE; 1st Part Field: GND; CLASS: IO; FPLIST: MILLMAX2501,MILLMAX2501_ALT1; Manufacturer: MILL-MAX; Manufacturer PN: 2501-2-00-80-00-00-07-0; PART_NUMBER: 260-0003; Part Number: MILL-MAX 2501-2-00-80-00-00-07-0
E4 = TESTPOINT_.219_MILL-MAX_2501: TEST POINT,TURRET,0.094",MTG. HOLE; 1st Part Field: EXTVCC; CLASS: IO; FPLIST: MILLMAX2501,MILLMAX2501_ALT1; Manufacturer: MILL-MAX; Manufacturer PN: 2501-2-00-80-00-00-07-0; PART_NUMBER: 260-0003; Part Number: MILL-MAX 2501-2-00-80-00-00-07-0
E5 = TESTPOINT_.219_MILL-MAX_2501: TEST POINT,TURRET,0.094",MTG. HOLE; 1st Part Field: VO_SNS+; CLASS: IO; FPLIST: MILLMAX2501,MILLMAX2501_ALT1; Manufacturer: MILL-MAX; Manufacturer PN: 2501-2-00-80-00-00-07-0; PART_NUMBER: 260-0003; Part Number: MILL-MAX 2501-2-00-80-00-00-07-0
E6 = TESTPOINT_.219_MILL-MAX_2501: TEST POINT,TURRET,0.094",MTG. HOLE; 1st Part Field: VO_SNS-; CLASS: IO; FPLIST: MILLMAX2501,MILLMAX2501_ALT1; Manufacturer: MILL-MAX; Manufacturer PN: 2501-2-00-80-00-00-07-0; PART_NUMBER: 260-0003; Part Number: MILL-MAX 2501-2-00-80-00-00-07-0
E10 = TESTPOINT_.219_MILL-MAX_2501: TEST POINT,TURRET,0.094",MTG. HOLE; 1st Part Field: PLLIN; CLASS: IO; FPLIST: MILLMAX2501,MILLMAX2501_ALT1; Manufacturer: MILL-MAX; Manufacturer PN: 2501-2-00-80-00-00-07-0; PART_NUMBER: 260-0003; Part Number: MILL-MAX 2501-2-00-80-00-00-07-0
E11 = TESTPOINT_.219_MILL-MAX_2501: TEST POINT,TURRET,0.094",MTG. HOLE; 1st Part Field: PGOOD; CLASS: IO; FPLIST: MILLMAX2501,MILLMAX2501_ALT1; Manufacturer: MILL-MAX; Manufacturer PN: 2501-2-00-80-00-00-07-0; PART_NUMBER: 260-0003; Part Number: MILL-MAX 2501-2-00-80-00-00-07-0
E13 = TESTPOINT_.219_MILL-MAX_2501: TEST POINT,TURRET,0.094",MTG. HOLE; 1st Part Field: FAULT; CLASS: IO; FPLIST: MILLMAX2501,MILLMAX2501_ALT1; Manufacturer: MILL-MAX; Manufacturer PN: 2501-2-00-80-00-00-07-0; PART_NUMBER: 260-0003; Part Number: MILL-MAX 2501-2-00-80-00-00-07-0
E14 = TESTPOINT_.219_MILL-MAX_2501: TEST POINT,TURRET,0.094",MTG. HOLE; 1st Part Field: RUN; CLASS: IO; FPLIST: MILLMAX2501,MILLMAX2501_ALT1; Manufacturer: MILL-MAX; Manufacturer PN: 2501-2-00-80-00-00-07-0; PART_NUMBER: 260-0003; Part Number: MILL-MAX 2501-2-00-80-00-00-07-0
J1 = BANANA_SMALL_0: CLASS: DISCRETE; Component: conn; Label: VIN; Manufacturer: PENNENGINEERING; Manufacturer PN: KFH-032-10ET; PART_NUMBER: 769-0005; Part Number: PEM KFH-032-10
J2 J4 = BANANA_SMALL_0: CLASS: DISCRETE; Component: conn; Label: GND; Manufacturer: PENNENGINEERING; Manufacturer PN: KFH-032-10ET; PART_NUMBER: 769-0005; Part Number: PEM KFH-032-10
J3 = BANANA_SMALL_0: CLASS: DISCRETE; Component: conn; Label: VOUT; Manufacturer: PENNENGINEERING; Manufacturer PN: KFH-032-10ET; PART_NUMBER: 769-0005; Part Number: PEM KFH-032-10
L1-L4 = IND_ALT: IND.,2uH,PWR. SHIELDED,20%,40A,1.34mOhms,19.69x19.55x10.67mm, SMD,AEC-Q200; CLASS: DISCRETE; Manufacturer: COILCRAFT; Manufacturer PN: SER2011-202MLB; PART_NUMBER: 200-0472; Package Size: 19.69x19.55x10.67mm, SMD; Tolerance: 20%
Q1 Q2 Q11 Q13 = BSC014N04LS: XSTR.,MOSFET, N-CH,80V,40A,TSDSON-8 FL; CLASS: DISCRETE; Manufacturer: INFINEON; PART_NUMBER: 240-0317; Package Size: 8-PowerVDFN; Package Type: TSDSON-8 FL; Part Number: INFINEON BSZ070N08LS5ATMA1; Polarity: MOSFET N-Channel, Metal Oxide; Rated Power: 80V; Rated Voltage: 80V
Q1A Q1A1 Q11A Q11A1 Q22A Q22A1-Q22A3 = 8P_N-CH_TYPE1C: XSTR., OPTION, MOSFET N-CH, PPAK SO-8; CLASS: DISCRETE; PART_NUMBER: 240-0311; Package Type: PPAK SO-8
Q3-Q6 Q9 Q10 Q15 Q16 = BSC014N04LS: XSTR.,MOSFET, N-CH,40V,98A,TDSON-8; CLASS: DISCRETE; Manufacturer: INFINEON; PART_NUMBER: 240-0252; Package Size: TDSON-8; Package Type: TDSON-8; Part Number: INFINEON BSC032N04LS; Polarity: N-Channel; Rated Voltage: 40V
Q7 Q8 Q12 Q14 = BSC014N04LS: XSTR.,MOSFET, N-CH,40V,100A,TDSON-8 FL; CLASS: DISCRETE; Manufacturer: INFINEON; PART_NUMBER: 240-0251; Package Type: TDSON-8 FL; Part Number: INFINEON BSC014N04LSI; Rated Voltage: 40V
Q22 Q26 Q30 Q34 = BSC014N04LS: XSTR.,MOSFET, N-CH,80V,40A,TSDSON-8 FL; BOM Notes: NO STUFF; CLASS: DISCRETE; Manufacturer: INFINEON; Manufacturer PN: BSZ070N08LS5; PART_NUMBER: 240-0311; Package Size: 8-PowerVDFN; Package Type: TSDSON-8 FL; Part Number: INFINEON BSZ070N08LS5ATMA1; Polarity: MOSFET N-Channel, Metal Oxide; Rated Power: 80V; Rated Voltage: 80V
Q23 Q24 Q27 = BSC014N04LS: XSTR., OPTION, MOSFET N-CH, PG-TDSON-8; CLASS: DISCRETE; PART_NUMBER: 240-0350; Package Size: TDSON-8; Package Type: TDSON-8; Polarity: N-Channel
Q25 Q29 Q33 Q37 = BSC014N04LS: XSTR.,MOSFET, N-CH,40V,100A,TDSON-8 FL; BOM Notes: NO STUFF; CLASS: DISCRETE; Manufacturer: INFINEON; Manufacturer PN: BSC014N04LSI; PART_NUMBER: 240-0311; Package Type: TDSON-8 FL; Part Number: INFINEON BSC014N04LSI; Rated Voltage: 40V
R1 R7 R19 R38 R42 R61 = RES: RES.,1k OHM,1%,1/10W,0603; CLASS: DISCRETE; FPLIST: CR0603N,CR0603L,CR0603M; Manufacturer: VISHAY; Manufacturer PN: CRCW06031K00FKEA; PART_NUMBER: 100-2422; Package Size: 0603; Part Number: VISHAY CRCW06031K00FKEA; Rated Power: 1/10W; Temperature Coefficient: 100ppm; Tolerance: 1%
R2 R36 R53 = RES: RES.,AEC-Q200,1 OHM,5%,1/10W,0603; CLASS: DISCRETE; FPLIST: CR0603N,CR0603L,CR0603M; Manufacturer: VISHAY; Manufacturer PN: CRCW06031R00JNEA; PART_NUMBER: 100-0271; Package Size: 0603; Part Number: VISHAY CRCW06031R00JNEA; Rated Power: 1/10W; Temperature Coefficient: 200ppm/C; Tolerance: 5%
R3 R31 R34 R44 R46 R65 R74 R234 R235 R250 R251 R253 R262 R263 R265 = RES: RES., OPTION, 0603; CLASS: DISCRETE; FPLIST: CR0603N,CR0603L,CR0603M; PART_NUMBER: 100-2374; Package Size: 0603; Part Number: OPTION
R5 R10-R12 R14 R20 R32 R33 R35 R40 R41 R45 R226-R230 R240 R241 R246 R252 R254-R256 R258 = RES: RES.,0 OHM,1/10W,0603; CLASS: DISCRETE; FPLIST: CR0603N,CR0603L,CR0603M; Manufacturer: VISHAY; Manufacturer PN: CRCW06030000Z0EA; PART_NUMBER: 100-0009; Package Size: 0603; Part Number: VISHAY CRCW06030000Z0EA; Rated Power: 1/10W
R6 = RES: RES.,AEC-Q200,1M OHM,1%,1/8W,0805; CLASS: DISCRETE; FPLIST: CR0805N,CR0805L,CR0805M; Manufacturer: VISHAY; Manufacturer PN: CRCW08051M00FKEA; PART_NUMBER: 100-2835; Package Size: 0805; Part Number: VISHAY CRCW08051M00FKEA; Rated Power: 1/8W; Temperature Coefficient: +/-100ppm; Tolerance: 1%
R8 = RES: RES.,34k OHMS,1%,1/10W,0603; CLASS: DISCRETE; FPLIST: CR0603N,CR0603L,CR0603M; Manufacturer: PANASONIC; Manufacturer PN: ERJ3EKF3402V; PART_NUMBER: 100-0033; Package Size: 0603; Part Number: VISHAY CRCW060329K4FKEA; Rated Power: 1/10W; Temperature Coefficient: 100ppm/C; Tolerance: 1%
R9 R13 R22 R49 = RES: RES.,AEC-Q200,10k OHMS,1%,1/10W,0603; CLASS: DISCRETE; FPLIST: CR0603N,CR0603L,CR0603M; Manufacturer: VISHAY; Manufacturer PN: CRCW060310K0FKEA; PART_NUMBER: 100-2012; Package Size: 0603; Part Number: VISHAY CRCW060310K0FKEA; Rated Power: 1/10W; Temperature Coefficient: +/-100ppm/C; Tolerance: 1%
R15 R37 = RES: RES.,100k OHMS,1%,1/10W,0603; CLASS: DISCRETE; FPLIST: CR0603N,CR0603L,CR0603M; Manufacturer: VISHAY; Manufacturer PN: CRCW0603100KFKEA; PART_NUMBER: 100-0343; Package Size: 0603; Part Number: VISHAY CRCW0603100KFKEA; Rated Power: 1/10W; Temperature Coefficient: +/-100ppm; Tolerance: 1%
R16 R48 R64 R68 = RES: RES.,53.6k OHMS,1%,1/10W,0603,AEC-Q200; CLASS: DISCRETE; FPLIST: CR0603N,CR0603L,CR0603M; Inventory Qty: 9961; Manufacturer: VISHAY; Manufacturer PN: CRCW060353K6FKEA; PART_NUMBER: 100-0233; Package Size: 0603; Part Number: VISHAY CRCW060353K6FKEA; Rated Power: 1/10W; Temperature Coefficient: 100ppm/C; Tolerance: 1%
R17 R43 R70 = RES: RES.,AEC-Q200,6.81k OHMS,1%,1/8W,0805; CLASS: DISCRETE; FPLIST: CR0805N,CR0805L,CR0805M; Manufacturer: VISHAY; Manufacturer PN: CRCW08056K81FKEA; PART_NUMBER: 100-0993; Package Size: 0805; Part Number: VISHAY CRCW08056K81FKEA; Rated Power: 1/8W; Temperature Coefficient: 100ppm; Tolerance: 1%
R18 = RES: RES.,3.74k OHMS,1%,1/10W,0603; CLASS: DISCRETE; FPLIST: CR0603N,CR0603L,CR0603M; Inventory Qty: 0; Manufacturer: VISHAY; Manufacturer PN: CRCW06033K74FKEA; PART_NUMBER: 100-1378; Package Size: 0603; Part Number: VISHAY CRCW06033K74FKEA; Rated Power: 1/10W; Temperature Coefficient: 100ppm/C; Tolerance: 1%
R23 R75 R244 R259 = RES: RES.,AEC-Q200,60.4k OHMS,1%,1/10W,0603; CLASS: DISCRETE; FPLIST: CR0603N,CR0603L,CR0603M; Manufacturer: VISHAY; Manufacturer PN: CRCW060360K4FKEA; PART_NUMBER: 100-2367; Package Size: 0603; Part Number: VISHAY CRCW080560K4FKEA; Rated Power: 1/10W; Temperature Coefficient: 100ppm/C; Tolerance: 1%
R25 R66 R245 R248 = RES: RES.,AEC-Q200,4.32k OHMS,1%,1/10W,0603; CLASS: DISCRETE; FPLIST: CR0603N,CR0603L,CR0603M; Manufacturer: VISHAY; Manufacturer PN: CRCW06034K32FKEA; PART_NUMBER: 100-0038; Package Size: 0603; Part Number: VISHAY CRCW06034K32FKEA; Rated Power: 1/10W; Temperature Coefficient: 100ppm/C; Tolerance: 1%
R24 R47 R50 R51 R76 R231 R264 R266-R268 R270 R271 R273-R276 R278 R279 = RES: RES.,0 OHM,1/10W,0603,AEC-Q200; CLASS: DISCRETE; FPLIST: CR0603N,CR0603L,CR0603M; Manufacturer: VISHAY; Manufacturer PN: CRCW06030000Z0EA; PART_NUMBER: 100-0009; Package Size: 0603; Part Number: VISHAY CRCW06030000Z0EA; Rated Power: 1/10W
RN1-RN4 = THERMISTOR-GENERAL: THERMISTOR, OPTION, 0603; CLASS: DISCRETE; FPLIST: CR0603N,CR0603L,CR0603M; PART_NUMBER: 122-0005; Package Size: 0603
SW1 = SW-SLD-SPDT: SWITCH,SLIDE,DPDT,0.3A,6VDC,PTH; CLASS: DISCRETE; Manufacturer: C&K; Manufacturer PN: JS202011CQN; PART_NUMBER: 430-0039; Part Number: C&K JS202011CQN
U1-U4 = LTC7821EUH: IC, Hybrid Step-Down Synchronous Controller QFN-32; CLASS: IC; Manufacturer: LINEAR TECH.; Manufacturer PN: LTC7821EUH#PBF; PART_NUMBER: LTC7821EUH#PBF; Package Size: QFN 32; Part Number: LINEAR TECH. LTC7821EUH#PBF
C287 C288 = CAP: CAP.,0.1uF,X7S,100V,10%,0603; CLASS: DISCRETE; Dielectric Type: X7S; FPLIST: CC0603N,CC0603L,CC0603M; Inventory Qty: 0; Manufacturer: TAIYO YUDEN; Manufacturer PN: HMK107C7104KA-T; PART_NUMBER: 150-0493; Package Size: 0603; Part Number: OPTION; Rated Voltage: 100V; Tolerance: 10%; UserField01: OPTION
Q28 Q31 Q32 Q35 Q36 = BSC014N04LS: XSTR.,MOSFET, N-CH,40V,98A,TDSON-8; BOM Notes: NO STUFF; CLASS: DISCRETE; Manufacturer: INFINEON; Manufacturer PN: BSC032N04LS; PART_NUMBER: 240-0350; Package Size: TDSON-8; Package Type: TDSON-8; Part Number: INFINEON BSC032N04LS; Polarity: N-Channel; Rated Voltage: 40V
R28 R60 R62 R272 R277 = RES: RES.,10k OHMS,1%,1/10W,0603,AEC-Q200; CLASS: DISCRETE; FPLIST: CR0603N,CR0603L,CR0603M; Manufacturer: VISHAY; Manufacturer PN: CRCW060310K0FKEA; PART_NUMBER: 100-2012; Package Size: 0603; Part Number: VISHAY CRCW060310K0FKEA; Rated Power: 1/10W; Temperature Coefficient: +/-100ppm/C; Tolerance: 1%
R52 R57 = RES: RES.,100k OHMS,1%,1/10W,0603,AEC-Q200; CLASS: DISCRETE; FPLIST: CR0603N,CR0603L,CR0603M; Manufacturer: VISHAY; Manufacturer PN: CRCW0603100KFKEA; PART_NUMBER: 100-0343; Package Size: 0603; Part Number: VISHAY CRCW0603100KFKEA; Rated Power: 1/10W; Temperature Coefficient: +/-100ppm; Tolerance: 1%
C52 C53 = CAP: CAP.,22uF,X5R,25V,10%,1210; CLASS: DISCRETE; Dielectric Type: X5R; FPLIST: CC1210N,CC1210L,CC1210M; Manufacturer: MURATA; Manufacturer PN: GRM32ER61E226KE15L; PART_NUMBER: 150-3033; Package Size: 1210; Package Type: SMD; Part Number: MURATA GRM32ER61E226KE15L; Rated Voltage: 25V; Tolerance: 10%
C54 = CAP: CAP.,0.047uF,X7R,25V,10%,0603; CLASS: DISCRETE; Dielectric Type: X7R; FPLIST: CC0603N,CC0603L,CC0603M; Manufacturer: MURATA; Manufacturer PN: GRM188R71E473KA01D; PART_NUMBER: 150-0063; Package Size: 0603; Part Number: MURATA GRM188R71E473KA01D; Rated Voltage: 25V; Tolerance: 10%
C55 = CAP: CAP.,220pF,C0G,50V,5%,0603; CLASS: DISCRETE; Dielectric Type: C0G; FPLIST: CC0603N,CC0603L,CC0603M; Manufacturer: MURATA; Manufacturer PN: GRM1885C1H221JA01D; PART_NUMBER: 150-0031; Package Size: 0603; Part Number: MURATA GRM1885C1H221JA01J; Rated Voltage: 50V; Tolerance: 5%
D16 = DIODE_SCHOTTKY_A: DIODE,SCHOTTKY,40V,250mW,SOD-323; CLASS: DISCRETE; FPLIST: SOD323,SOD-323N,SOD-323M; Manufacturer: CENTRAL SEMI; Manufacturer PN: CMDSH-4E TR Lead Free; Max Forward Current or Rated Power: 200mA; PART_NUMBER: 210-0247; Package Type: SOD-323; Part Number: CENTRAL SEMI. CMDSH-4E TR; Rated Voltage: 40V; Rated Voltage or Zener Voltage: 40V
E8 = TESTPOINT_.219_MILL-MAX_2501: TEST POINT,TURRET,0.094",MTG. HOLE; 1st Part Field: IO_CLK; CLASS: IO; FPLIST: MILLMAX2501,MILLMAX2501_ALT1; Manufacturer: MILL-MAX; Manufacturer PN: 2501-2-00-80-00-00-07-0; PART_NUMBER: 260-0003; Part Number: MILL-MAX 2501-2-00-80-00-00-07-0
E12 = TESTPOINT_.219_MILL-MAX_2501: TEST POINT,TURRET,0.094",MTG. HOLE; 1st Part Field: CLKOUT4; CLASS: IO; FPLIST: MILLMAX2501,MILLMAX2501_ALT1; Manufacturer: MILL-MAX; Manufacturer PN: 2501-2-00-80-00-00-07-0; PART_NUMBER: 260-0003; Part Number: MILL-MAX 2501-2-00-80-00-00-07-0
J5 = BNC_50_OHM_112404_B: CONN.,RF, BNC,RCPT JACK,5-PIN,STR, THT,50 Ohms; 1st Part Field: VOUT; CLASS: IO; Manufacturer: AMPHENOL RF; Manufacturer PN: 112404; PART_NUMBER: 250-0427; Part Number: CONNEX 112404
J6 = BNC_50_OHM_112404_B: CONN.,RF, BNC,RCPT JACK,5-PIN,STR, THT,50 Ohms; 1st Part Field: IOSTEP; CLASS: IO; Manufacturer: AMPHENOL RF; Manufacturer PN: 112404; PART_NUMBER: 250-0427; Part Number: CONNEX 112404
JP2 = 1X3_A: CONN.,HDR,MALE,1x3,2mm,STR, THT,NO SUBS. ALLOWED; 11th Part Field: OFF; 12th Part Field: BIAS1; 9th Part Field: ON; CLASS: IO; Manufacturer: Wurth Elektronik; Manufacturer PN: 62000311121; PART_NUMBER: 250-0639; Part Number: WURTH ELEKTRONIK 6200031121
L5 = IND: IND.,68uH,PWR, SHIELDED,20%,0.74A,0.42 OHM,2424, LPS6225; 1st Part Field: LPS6225-683MRB; CLASS: DISCRETE; Manufacturer: Coilcraft; Manufacturer PN: LPS6225-683MRB; PART_NUMBER: 200-0477; Package Size: 2424, LPS6225; Part Number: COILCRAFT LPS6225-683MRB; Tolerance: 20%
Q20 Q21 = 3P_N-CH_TYPE2A: XSTR.,MOSFET, N-CH,40V,TO-252 (DPAK); CLASS: DISCRETE; FPLIST: TO-252-3N,TO-252-3L,TO-252-3M; Manufacturer: VISHAY; Manufacturer PN: SUD50N04-8M8P-4GE3; PART_NUMBER: 240-0021; Package Type: TO-252 (DPAK); Part Number: VISHAY SILICONIX SUD50N04-8M8P-4GE3; Rated Voltage: 40V
R26 = RES: RES.,182k OHMS,1%,1/10W,0603,AEC-Q200; CLASS: DISCRETE; FPLIST: CR0603N,CR0603L,CR0603M; Manufacturer: PANASONIC; Manufacturer PN: ERJ3EKF1823V; PART_NUMBER: 100-2770; Package Size: 0603; Part Number: PANASONIC ERJ3EKF1823V; Rated Power: 1/10W; Temperature Coefficient: 100ppm/C; Tolerance: 1%
R27 = RES: RES.,20k OHMS,5%,1/10W,0603,AEC-Q200; CLASS: DISCRETE; FPLIST: CR0603N,CR0603L,CR0603M; Manufacturer: VISHAY; Manufacturer PN: CRCW060320K0JNEA; PART_NUMBER: 100-0160; Package Size: 0603; Part Number: VISHAY CRCW060320K0JNEA; Rated Power: 1/10W; Temperature Coefficient: 200ppm/C; Tolerance: 5%
R29 = RES: RES.,80.6k OHMS,1%,1/10W,0603; CLASS: DISCRETE; FPLIST: CR0603N,CR0603L,CR0603M; Manufacturer: VISHAY; Manufacturer PN: CRCW060380K6FKEA; PART_NUMBER: 100-2503; Package Size: 0603; Part Number: VISHAY CRCW060380K6FKEA; Rated Power: 1/10W; Temperature Coefficient: 100ppm/C; Tolerance: 1%
R30 R247 = RES: RES.,0.2 OHM,1%,1/2W,2010,SENSE, AEC-Q200; CLASS: DISCRETE; FPLIST: CR2010N,CR2010L,CR2010M; Manufacturer: VISHAY; Manufacturer PN: WSL2010R2000FEA; PART_NUMBER: 100-1095; Package Size: 2010; Part Number: VISHAY WSL2010R2000FEA; Rated Power: 1/2W; Temperature Coefficient: +/-75ppm; Tolerance: 1%
R56 = RES: RES.,1 OHM,5%,1/10W,0603,AEC-Q200; CLASS: DISCRETE; FPLIST: CR0603N,CR0603L,CR0603M; Manufacturer: VISHAY; Manufacturer PN: CRCW06031R00JNEA; PART_NUMBER: 100-0271; Package Size: 0603; Part Number: VISHAY CRCW06031R00JNEA; Rated Power: 1/10W; Temperature Coefficient: 200ppm/C; Tolerance: 5%
R58 R59 = RES: RES.,1k OHM,1%,1/10W,0603,AEC-Q200; CLASS: DISCRETE; FPLIST: CR0603N,CR0603L,CR0603M; Manufacturer: VISHAY; Manufacturer PN: CRCW06031K00FKEA; PART_NUMBER: 100-2422; Package Size: 0603; Part Number: VISHAY CRCW06031K00FKEA; Rated Power: 1/10W; Temperature Coefficient: 100ppm; Tolerance: 1%
R71 = RES: RES.,6.81k OHMS,1%,1/8W,0805,AEC-Q200; CLASS: DISCRETE; FPLIST: CR0805N,CR0805L,CR0805M; Manufacturer: VISHAY; Manufacturer PN: CRCW08056K81FKEA; PART_NUMBER: 100-0993; Package Size: 0805; Part Number: VISHAY CRCW08056K81FKEA; Rated Power: 1/8W; Temperature Coefficient: 100ppm; Tolerance: 1%
U7 = LTC3630A-MSE: IC, SYNCHRONOUS STEP-DOWN CONVERTER; CLASS: IC; Manufacturer: LINEAR TECH.; Manufacturer PN: LTC3630AEMSE#TRPBF; PART_NUMBER: LTC3630AEMSE#PBF; Package Size: MSE16; Part Number: LINEAR TECH. LTC3630AEMSE
XJP2 = SHUNT_2MM: CONN.,SHUNT,FEMALE,2 POS,2mm; CLASS: IO; Manufacturer: Wurth Elektronik; Manufacturer PN: 60800213421; PART_NUMBER: 250-0485; Part Number: WURTH ELEKTRONIK 60800213421
JLRE1-JLRE4 = Lug_Ring: RING, LUG, CRIMP,#10,NON-INSULATED,SOLDERLESS TERMINALS; CLASS: DISCRETE; Manufacturer: KEYSTONE; Manufacturer PN: 8205; PART_NUMBER: 769-0010; Part Number: KEYSTONE 8205
JNE1-JNE8 = NUT: NUT,HEX,#10-32,BRASS; CLASS: DISCRETE; Manufacturer: PENCOM; Manufacturer PN: NU1132; PART_NUMBER: 761-0013; Part Number: PENCOM NU1132
JWE1-JWE4 = Washer: WASHER,#10,LOCK,EXT,TIN FINISH; CLASS: DISCRETE; Manufacturer: PENCOM; Manufacturer PN: WA4526; PART_NUMBER: 762-0021; Part Number: PENCOM WA4526
LB1 = BLANK_LABEL: LABEL SPEC, DEMO BOARD SERIAL NUMBER; Manufacturer: BRADY; Manufacturer PN: THT-96-717-10; PART_NUMBER: 895-0154
MH1-MH6 = CON1: STANDOFF,NYLON,SNAP-ON,0.625"; CLASS: DISCRETE; Manufacturer: KEYSTONE; Manufacturer PN: 8834; PART_NUMBER: 763-0013; Part Number: KEYSTONE 8834
PCB1 = BLANK_PCB_PART: BOM Notes: REV03; CLASS: DISCRETE; Manufacturer: PHASE 3 TECHNOLOGIES INC.; Manufacturer PN: 600-DC2787A; PART_NUMBER: 600-DC2787A
STNCL1 = BLANK_STENCIL_PART: BOM Notes: REV03; CLASS: DISCRETE; Manufacturer: Analog Devices Inc.; Manufacturer PN: 830-DC2787A; PART_NUMBER: 830-DC2787A

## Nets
+8V: C51.1 C52.1 C53.1 L5.2 R24.1 R26.2
GND: C1.2 C2.2 C3.2 C4.1 C5.1 C6.2 C7.2 C10.2 C11.2 C12.1 C13.1 C15.2 C16.1 C17.2 C29.2 C30.2 C31.2 C32.2 C33.2 C34.2 C35.2 C36.2 C41.2 C42.2 C43.2 C44.2 C47.2 C49.2 C50.1 C52.2 C53.2 C54.2 C55.2 C56.2 C57.2 C58.2 C59.2 C60.2 C61.2 C62.2 C63.2 C68.2 C69.2 C70.2 C71.2 C72.2 C73.2 C74.2 C79.2 C80.2 C81.2 C82.2 C83.2 C84.2 C85.2 C86.2 C87.2 C88.2 C89.2 C90.2 C91.1 C92.2 C93.2 C94.2 C95.1 C97.2 C98.2 C99.2 C100.2 C101.2 C103.2 C104.2 C105.2 C107.2 C109.2 C119.2 C125.2 C126.2 C127.2 C128.2 C129.2 C130.2 C131.2 C132.2 C133.2 C136.2 C137.2 C138.2 C139.2 C140.2 C141.2 C142.2 C143.2 C148.2 C149.2 C150.2 C152.2 C153.2 C154.2 C155.2 C166.2 C174.1 C175.1 C176.2 C179.2 C180.2 C181.2 C182.2 C183.2 C184.2 C191.2 C192.2 C193.2 C194.2 C195.2 C196.2 C197.2 C198.2 C203.2 C206.2 C207.2 C208.2 C209.2 C210.2 C216.2 C255.2 C256.2 C257.2 C258.2 C259.2 C260.2 C261.2 C262.2 E2.1 E3.1 E6.1 E9.1 E15.1 J2.1(TP) J4.1(TP) J5.2 J5.3 J5.4 J5.5 J6.2 J6.3 J6.4 J6.5 JP2.3 Q7.1 Q7.2 Q7.3 Q8.1 Q8.2 Q8.3 Q12.1 Q12.2 Q12.3 Q14.1 Q14.2 Q14.3 Q25.1 Q25.2 Q25.3 Q29.1 Q29.2 Q29.3 Q33.1 Q33.2 Q33.3 Q37.1 Q37.2 Q37.3 R8.2 R27.1 R28.2 R29.2 R30.2 R247.2 SW1.3 U1.17(PGND) U2.17(PGND) U3.17(PGND) U4.17(PGND) U7.6(VPRG2) U7.7(VPRG1) U7.8(GND) U7.14(GND) U7.16(GND) U7.17(GND)
GND_SIGNAL: C26.1 C37.1 C39.1 C45.1 C48.1 C110.1 C120.1 C156.1 C157.1 C158.1 C160.1 C169.1 C172.1 C215.1 C287.1 C288.1 C290.1 C291.1 C293.1 C295.1 R15.2 R16.2 R25.2 R32.1 R33.2 R35.1 R37.2 R45.1 R46.1 R47.1 R48.2 R52.2 R57.2 R64.2 R66.2 R68.2 R245.2 R248.2 R250.1 R251.1 R253.1 R262.1 R263.1 R265.1 RN1.1 RN2.1 RN3.1 RN4.1 U1.33(SGND) U2.33(SGND) U3.33(SGND) U4.33(SGND)
VIN: C1.1 C2.1 C3.1 C6.1 C7.1 C47.1 C49.1 C56.1 C58.1 C59.1 C68.1 C69.1 C70.1 C71.1 C72.1 C73.1 C74.1 C85.1 C86.1 C87.1 C88.1 C103.1 C104.1 C105.1 C109.1 C119.1 C153.1 C154.1 C203.1 C206.1 C207.1 C208.1 C209.1 C210.1 E1.1 J1.1(TP) Q1.5 Q1.6 Q1.7 Q1.8 Q1A.5(D) Q1A.6(D) Q1A.7(D) Q1A.8(D) Q1A1.5(D) Q1A1.6(D) Q1A1.7(D) Q1A1.8(D) Q2.5 Q2.6 Q2.7 Q2.8 Q11.5 Q11.6 Q11.7 Q11.8 Q11A.5(D) Q11A.6(D) Q11A.7(D) Q11A.8(D) Q11A1.5(D) Q11A1.6(D) Q11A1.7(D) Q11A1.8(D) Q13.5 Q13.6 Q13.7 Q13.8 Q22.5 Q22.6 Q22.7 Q22.8 Q22A.5(D) Q22A.6(D) Q22A.7(D) Q22A.8(D) Q22A1.5(D) Q22A1.6(D) Q22A1.7(D) Q22A1.8(D) Q22A2.5(D) Q22A2.6(D) Q22A2.7(D) Q22A2.8(D) Q22A3.5(D) Q22A3.6(D) Q22A3.7(D) Q22A3.8(D) Q26.5 Q26.6 Q26.7 Q26.8 Q30.5 Q30.6 Q30.7 Q30.8 Q34.5 Q34.6 Q34.7 Q34.8 R1.1 R2.1 R6.1 R19.1 R36.1 R38.1 R53.1 R56.1 R58.1 U7.3(VIN)
CLKOUT1: R252.2 U1.2(CLKOUT)
CLKOUT2: R76.2 U2.2(CLKOUT)
CLKOUT3: R264.2 U3.2(CLKOUT)
CLKOUT4: E12.1 U4.2(CLKOUT)
EXTVCC: C256.1 C258.1 C260.1 C262.1 E4.1 R3.1 R24.2 U1.16(EXTVCC) U2.16(EXTVCC) U3.16(EXTVCC) U4.16(EXTVCC)
FAULT: E13.1 R270.2 R273.2 R275.2 R278.2
INTVCC1: C255.1 D3.2(A) R9.1 R13.1 R31.1 U1.8(EXT_REF) U1.19(INTVCC)
INTVCC2: C257.1 D4.2(A) R34.1 R49.1 R272.1 U2.8(EXT_REF) U2.19(INTVCC)
INTVCC3: C259.1 D13.2(A) R22.1 R44.1 R62.1 U3.8(EXT_REF) U3.19(INTVCC)
INTVCC4: C261.1 D14.2(A) R60.1 R74.1 R277.1 U4.8(EXT_REF) U4.19(INTVCC)
ITH: R240.2 R241.2 R255.2 R267.2
PGOOD: E11.1 R271.2 R274.2 R276.2 R279.2
RUN: C16.2 E14.1 R6.2 R8.1 R226.2 R228.2 R229.2 R231.2 SW1.1 SW1.2
TRACK/SS: R227.2 R230.2 R254.2 R266.2
VFB: R246.2 R256.2 R258.2 R268.2
VOUT: C10.1 C11.1 C40.1 C41.1 C42.1 C43.1 C44.1 C50.2 C57.1 C81.1 C82.1 C83.1 C84.1 C89.1 C97.1 C98.1 C99.1 C100.1 C101.1 C108.1 C125.1 C139.1 C152.1 C155.1 C167.1 C170.1 C176.1 C193.1 C194.1 C216.1 E5.1 J3.1(TP) J5.1 L1.2 L2.2 L3.2 L4.2 Q20.2(D) Q21.2(D) R3.2 R20.2 U1.14(ISENSE-) U2.14(ISENSE-) U3.14(ISENSE-) U4.14(ISENSE-)
VOUTA: C46.2 C171.2 C292.2 C294.2 R20.1 R23.1 R75.1 R244.2 R259.2
N04686: R15.1 U1.9(HYS_PRGM)
N04784: C46.1 C48.2 R23.2 R25.1 R246.1 U1.13(VFB)
N04800: R16.1 U1.11(FREQ)
N04822: C45.2 R18.1 R240.1 U1.10(ITH)
N04982: R31.2 R32.2 RN1.2 U1.12(TEMP)
N05002: C5.2 R2.2 U1.28(VIN)
N05034: Q1.4(GATE) Q1A.4(G) Q22.4(GATE) Q22A.4(G) U1.30(TG1)
N05038: C27.1 D2.2(A) D3.1(C) R10.2
N05496: C8.2 C18.1 C19.1 C20.1 C21.1 C22.1 C23.1 C24.1 C25.1 C64.1 C65.1 C66.1 C67.1 Q1.1 Q1.2 Q1.3 Q1A.1(S) Q1A.2(S) Q1A.3(S) Q3.5 Q3.6 Q3.7 Q3.8 Q22.1 Q22.2 Q22.3 Q22A.1(S) Q22A.2(S) Q22A.3(S) Q23.5 Q23.6 Q23.7 Q23.8 U1.29(SW1)
N05534: C4.2 R1.2 U1.27(VINSENSE)
N05654: R10.1 U1.22(BOOST3)
N05678: C18.2 C19.2 C20.2 C21.2 C22.2 C23.2 C24.2 C25.2 C27.2 C64.2 C65.2 C66.2 C67.2 L1.1 Q5.1 Q5.2 Q5.3 Q7.5 Q7.6 Q7.7 Q7.8 Q24.1 Q24.2 Q24.3 Q25.5 Q25.6 Q25.7 Q25.8 R17.2 U1.20(SW3)
N05750: C40.2 R17.1 U1.15(ISENSE+)
N05808: Q3.4(GATE) Q23.4(GATE) U1.24(BG1)
N06198: Q5.4(GATE) Q24.4(GATE) U1.21(TG2)
N06202: Q7.4(GATE) Q25.4(GATE) U1.18(BG2)
N06246: C9.2 C29.1 C30.1 C31.1 C32.1 C33.1 C34.1 C35.1 C36.1 C60.1 C61.1 C62.1 C63.1 Q3.1 Q3.2 Q3.3 Q5.5 Q5.6 Q5.7 Q5.8 Q23.1 Q23.2 Q23.3 Q24.5 Q24.6 Q24.7 Q24.8 R7.2 U1.25(MID)
N06460: R5.1 U1.31(BOOST1)
N06468: C8.1 D1.1(C) R5.2
N06760: C9.1 D1.2(A) D2.1(C) U1.23(BOOST2)
N06948: C15.1 R7.1 U1.26(MIDSENSE)
N07504: C39.2 R18.2
N08326: R9.2 R270.1 U1.4(\\~{FAULTB})
N08814: R12.1 R33.1 U1.1(MODE/PLLIN)
N08826: C26.2 U1.6(TIMER)
N09082: C37.2 R227.1 U1.7(TRACK/SS)
N127229: R13.2 R271.1 U1.5(PGOOD)
N154266: R34.2 R35.2 RN2.2 U2.12(TEMP)
N154822: R37.1 U2.9(HYS_PRGM)
N154910: R48.1 U2.11(FREQ)
N154914: C110.2 R234.2 R255.1 U2.10(ITH)
N154980: C91.2 R36.2 U2.28(VIN)
N155028: Q11.4(GATE) Q11A.4(G) Q22A1.4(G) Q26.4(GATE) U2.30(TG1)
N155032: C96.1 D4.1(C) D5.2(A) R40.2
N155198: C106.2 C111.1 C113.1 C114.1 C115.1 C121.1 C122.1 C123.1 C124.1 C144.1 C145.1 C146.1 C147.1 Q9.5 Q9.6 Q9.7 Q9.8 Q11.1 Q11.2 Q11.3 Q11A.1(S) Q11A.2(S) Q11A.3(S) Q22A1.1(S) Q22A1.2(S) Q22A1.3(S) Q26.1 Q26.2 Q26.3 Q27.5 Q27.6 Q27.7 Q27.8 U2.29(SW1)
N155218: C95.2 R38.2 U2.27(VINSENSE)
N155328: R40.1 U2.22(BOOST3)
N155332: C96.2 C111.2 C113.2 C114.2 C115.2 C121.2 C122.2 C123.2 C124.2 C144.2 C145.2 C146.2 C147.2 L2.1 Q8.5 Q8.6 Q8.7 Q8.8 Q10.1 Q10.2 Q10.3 Q28.1 Q28.2 Q28.3 Q29.5 Q29.6 Q29.7 Q29.8 R43.2 U2.20(SW3)
N155360: C108.2 R43.1 U2.15(ISENSE+)
N155626: Q10.4(GATE) Q28.4(GATE) U2.21(TG2)
N155630: Q8.4(GATE) Q29.4(GATE) U2.18(BG2)
N155670: C102.2 C126.1 C127.1 C128.1 C129.1 C130.1 C131.1 C132.1 C133.1 C140.1 C141.1 C142.1 C143.1 Q9.1 Q9.2 Q9.3 Q10.5 Q10.6 Q10.7 Q10.8 Q27.1 Q27.2 Q27.3 Q28.5 Q28.6 Q28.7 Q28.8 R42.2 U2.25(MID)
N155876: R41.1 U2.31(BOOST1)
N155884: C106.1 D6.1(C) R41.2
N156056: C102.1 D5.1(C) D6.2(A) U2.23(BOOST2)
N156150: C107.1 R42.1 U2.26(MIDSENSE)
N156490: C292.1 C293.2 R244.1 R245.1 R256.1 U2.13(VFB)
N156946: R49.2 R273.1 U2.4(\\~{FAULTB})
N157318: C120.2 U2.6(TIMER)
N157512: Q9.4(GATE) Q27.4(GATE) U2.24(BG1)
N16902404: R226.1 R250.2 U1.3(RUN)
N16902587: R228.1 R253.2 U2.3(RUN)
N16907128: C287.2 R254.1 U2.7(TRACK/SS)
N16927611: C290.2 R234.1
N17441633: E10.1 R12.2
N17479158: R251.2 R252.1 U2.1(MODE/PLLIN)
N17483911: C12.2 R19.2 U3.27(VINSENSE)
N17483921: C13.2 R53.2 U3.28(VIN)
N17483939: Q1A1.4(G) Q2.4(GATE) Q22A2.4(G) Q30.4(GATE) U3.30(TG1)
N17483945: R46.2 R76.1 U3.1(MODE/PLLIN)
N17483987: C14.2 C28.1 C38.1 C75.1 C76.1 C77.1 C78.1 C189.1 C190.1 C199.1 C200.1 C201.1 C202.1 Q1A1.1(S) Q1A1.2(S) Q1A1.3(S) Q2.1 Q2.2 Q2.3 Q4.5 Q4.6 Q4.7 Q4.8 Q22A2.1(S) Q22A2.2(S) Q22A2.3(S) Q30.1 Q30.2 Q30.3 Q31.5 Q31.6 Q31.7 Q31.8 U3.29(SW1)
N17484045: R14.1 U3.31(BOOST1)
N17484049: C14.1 D11.1(C) R14.2
N17484270: C173.1 D11.2(A) D12.1(C) U3.23(BOOST2)
N17484290: R229.1 R262.2 U3.3(RUN)
N17484292: R62.2 R275.1 U3.4(\\~{FAULTB})
N17484294: R22.2 R276.1 U3.5(PGOOD)
N17484350: Q4.4(GATE) Q31.4(GATE) U3.24(BG1)
N17484378: C79.1 C80.1 C90.1 C92.1 C93.1 C94.1 C173.2 C191.1 C192.1 C195.1 C196.1 C197.1 C198.1 Q4.1 Q4.2 Q4.3 Q6.5 Q6.6 Q6.7 Q6.8 Q31.1 Q31.2 Q31.3 Q32.5 Q32.6 Q32.7 Q32.8 R61.2 U3.25(MID)
N17484422: C17.1 R61.1 U3.26(MIDSENSE)
N17484515: C159.1 D12.2(A) D13.1(C) R11.2
N17484662: C28.2 C38.2 C75.2 C76.2 C77.2 C78.2 C159.2 C189.2 C190.2 C199.2 C200.2 C201.2 C202.2 L3.1 Q6.1 Q6.2 Q6.3 Q12.5 Q12.6 Q12.7 Q12.8 Q32.1 Q32.2 Q32.3 Q33.5 Q33.6 Q33.7 Q33.8 R70.2 U3.20(SW3)
N17484676: C158.2 U3.6(TIMER)
N17484678: R11.1 U3.22(BOOST3)
N17484842: Q6.4(GATE) Q32.4(GATE) U3.21(TG2)
N17484874: C169.2 R230.1 U3.7(TRACK/SS)
N17484934: Q12.4(GATE) Q33.4(GATE) U3.18(BG2)
N17485012: R52.1 U3.9(HYS_PRGM)
N17485014: C215.2 R65.1 R241.1 U3.10(ITH)
N17485016: R64.1 U3.11(FREQ)
N17485018: R44.2 R45.2 RN3.2 U3.12(TEMP)
N17485020: C171.1 C172.2 R66.1 R75.2 R258.1 U3.13(VFB)
N17485024: C170.2 R70.1 U3.15(ISENSE+)
N17485252: C160.2 R65.2
N17488097: Q11A1.4(G) Q13.4(GATE) Q22A3.4(G) Q34.4(GATE) U4.30(TG1)
N17488109: C175.2 R58.2 U4.27(VINSENSE)
N17488119: C174.2 R56.2 U4.28(VIN)
N17488137: C112.1 C116.1 C117.1 C118.1 C134.1 C135.1 C165.2 C177.1 C178.1 C185.1 C186.1 C187.1 C188.1 Q11A1.1(S) Q11A1.2(S) Q11A1.3(S) Q13.1 Q13.2 Q13.3 Q16.5 Q16.6 Q16.7 Q16.8 Q22A3.1(S) Q22A3.2(S) Q22A3.3(S) Q34.1 Q34.2 Q34.3 Q35.5 Q35.6 Q35.7 Q35.8 U4.29(SW1)
N17488257: R51.1 U4.31(BOOST1)
N17488261: C165.1 D16.1(C) R51.2
N17488447: R231.1 R265.2 U4.3(RUN)
N17488449: R60.2 R278.1 U4.4(\\~{FAULTB})
N17488459: R263.2 R264.1 U4.1(MODE/PLLIN)
N17488461: C164.1 D15.1(C) D16.2(A) U4.23(BOOST2)
N17488532: Q16.4(GATE) Q35.4(GATE) U4.24(BG1)
N17488556: C136.1 C137.1 C138.1 C148.1 C149.1 C150.1 C164.2 C179.1 C180.1 C181.1 C182.1 C183.1 C184.1 Q15.5 Q15.6 Q15.7 Q15.8 Q16.1 Q16.2 Q16.3 Q35.1 Q35.2 Q35.3 Q36.5 Q36.6 Q36.7 Q36.8 R59.2 U4.25(MID)
N17488596: C166.1 R59.1 U4.26(MIDSENSE)
N17488674: C162.1 D14.1(C) D15.2(A) R50.2
N17488797: C112.2 C116.2 C117.2 C118.2 C134.2 C135.2 C162.2 C177.2 C178.2 C185.2 C186.2 C187.2 C188.2 L4.1 Q14.5 Q14.6 Q14.7 Q14.8 Q15.1 Q15.2 Q15.3 Q36.1 Q36.2 Q36.3 Q37.5 Q37.6 Q37.7 Q37.8 R71.2 U4.20(SW3)
N17488807: C157.2 U4.6(TIMER)
N17488809: R50.1 U4.22(BOOST3)
N17488947: Q15.4(GATE) Q36.4(GATE) U4.21(TG2)
N17488975: C288.2 R266.1 U4.7(TRACK/SS)
N17489023: Q14.4(GATE) Q37.4(GATE) U4.18(BG2)
N17489093: R57.1 U4.9(HYS_PRGM)
N17489095: C156.2 R235.2 R267.1 U4.10(ITH)
N17489097: R68.1 U4.11(FREQ)
N17489099: R47.2 R74.2 RN4.2 U4.12(TEMP)
N17489101: C294.1 C295.2 R248.1 R259.1 R268.1 U4.13(VFB)
N17489105: C167.2 R71.1 U4.15(ISENSE+)
N17489404: C291.2 R235.1
N17516226: L5.1 U7.1(SW)
N17516326: C51.2 R26.1 R27.2 U7.9(VFB)
N17516344: JP2.2 U7.5(RUN)
N17516395: C55.1 R29.1 U7.11(ISET)
N17516403: C54.1 U7.10(SS)
N17517119: E8.1 Q20.1(G) Q21.1(G) R28.1
N17517140: J6.1 Q20.3(S) Q21.3(S) R30.1 R247.1
N17518463: R272.2 R274.1 U2.5(PGOOD)
N17521786: R277.2 R279.1 U4.5(PGOOD)

Not connected (* = marked no-connect by the designer): JP2 1; MH1 1; MH2 1; MH3 1; MH4 1; MH5 1; MH6 1; SW1 4 5 6; U1 32(NC); U2 32(NC); U3 32(NC); U4 32(NC); U7 12(FBO)

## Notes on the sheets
sheet 1
- HARDWARE
sheet 2
- SER2011-202MLD
- DYNAMIC LOAD CIRCUIT
- +8V BIAS
- DO NOT EXCEED
- 2% DUTY CYCLE MAX.
sheet 3
- SER2011-202MLD
sheet 4
- SER2011-202MLD
sheet 5
- REVISION HISTORY
- ECO
- REV
- DESCRIPTION
- DATE
- APPROVED
- 3
- PROD
- 02/20/19
- M M
- 40V~60V
- RUN
- ON
- OFF
- SER2011-202MLD
- 12V / 100A
- NOTES: UNLESS OTHERWISE SPECIFIED,
- 1.  CAPACITORS AND RESISTORS ARE 0603.
